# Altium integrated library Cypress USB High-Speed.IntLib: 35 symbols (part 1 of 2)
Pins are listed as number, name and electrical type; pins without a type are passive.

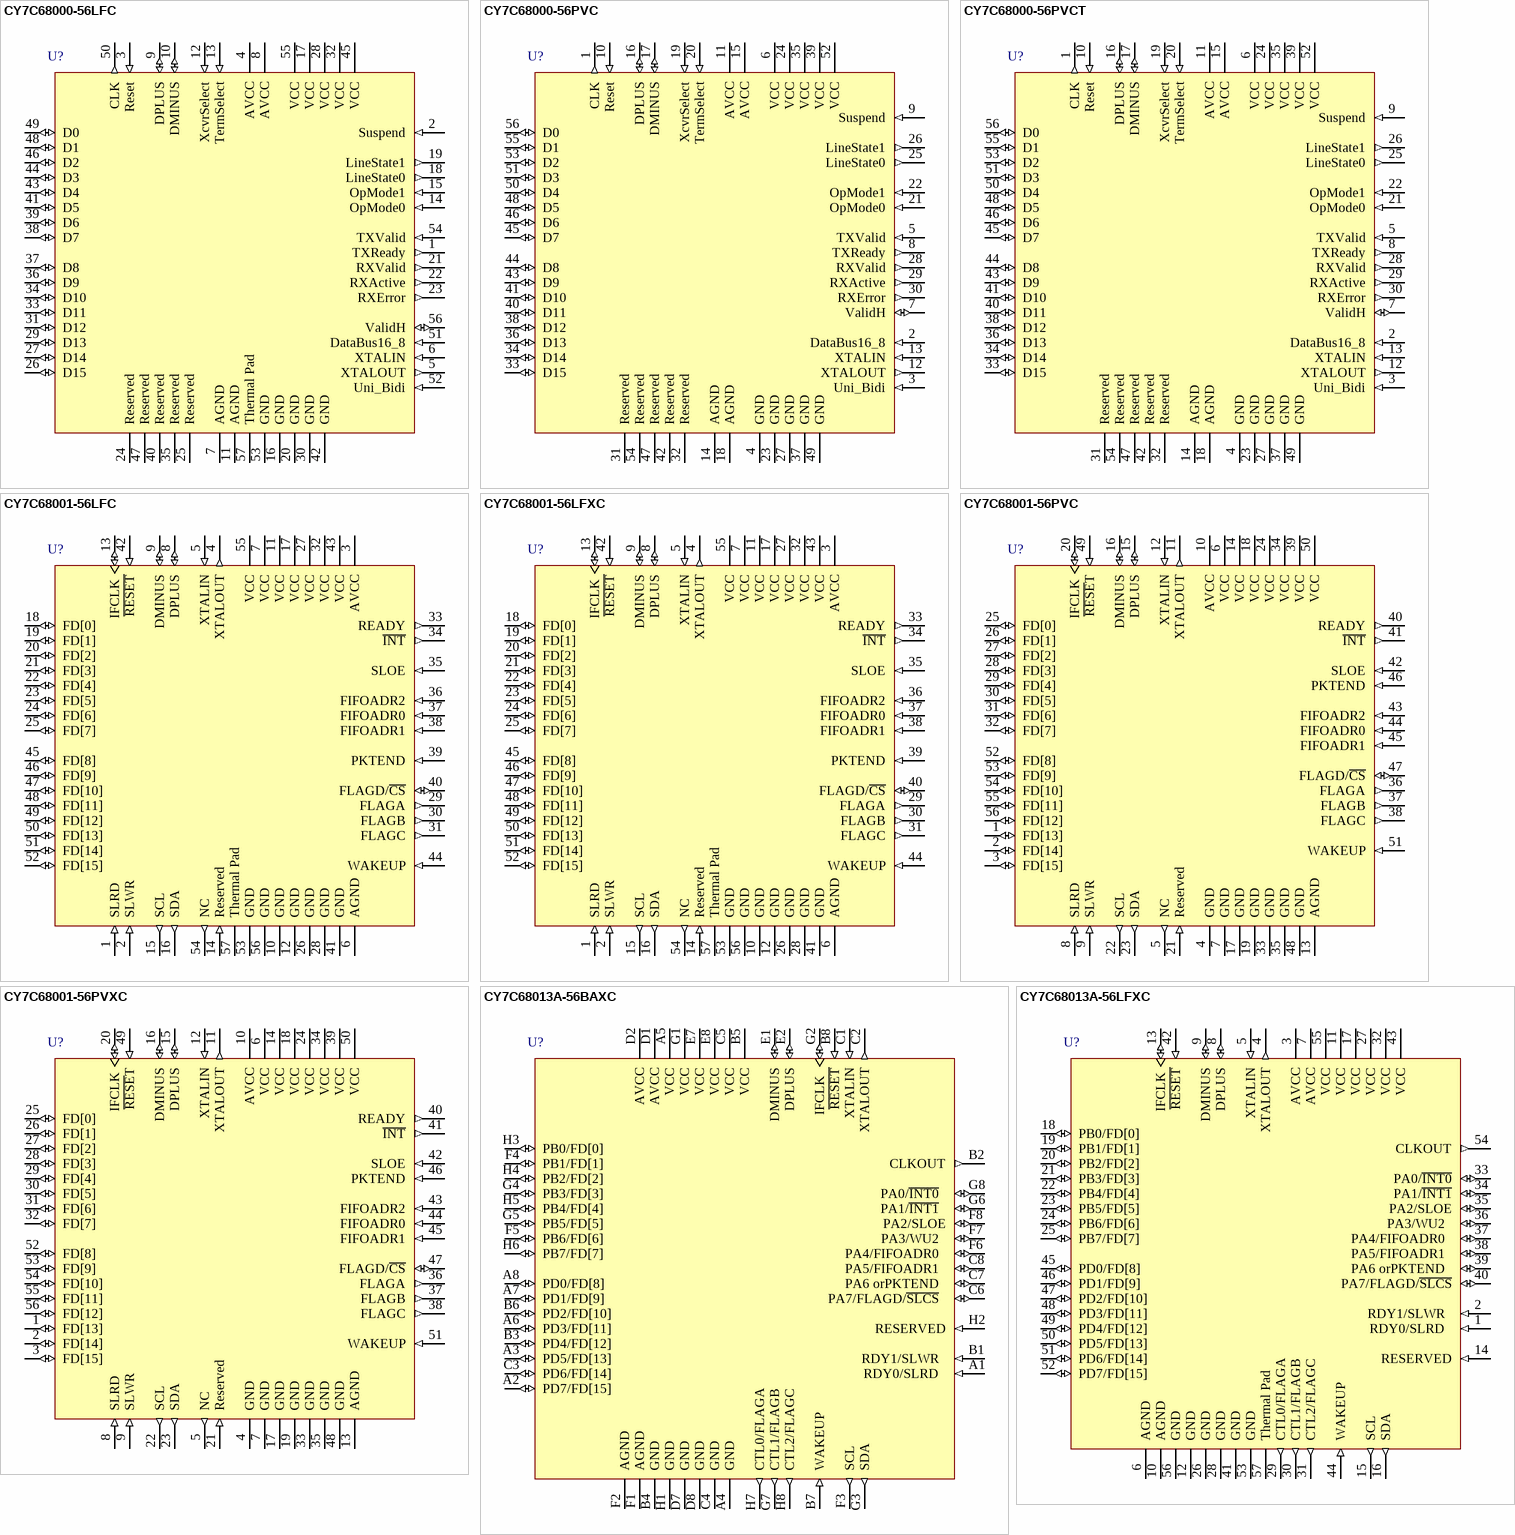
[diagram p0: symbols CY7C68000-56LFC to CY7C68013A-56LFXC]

## CY7C68000-56LFC
designator U?
TX2 USB2.0 Compliant with Transceiver Macrocell Interface Specification, 56-Pin QFN
footprint LS56B_N (QFN, 56-Leads, Body 8x8mm, Pitch 0.5mm, IPC Medium Density)
footprint LS56B_L (QFN, 56-Leads, Body 8x8mm, Pitch 0.5mm, IPC High Density)
footprint LS56B_M (QFN, 56-Leads, Body 8x8mm, Pitch 0.5mm, IPC Low Density)
pins: 1 TXReady (out), 2 Suspend (in), 3 Reset (in), 4 AVCC (power), 5 XTALOUT (out), 6 XTALIN (in), 7 AGND (power), 8 AVCC (power), 9 DPLUS (io), 10 DMINUS (io), 11 AGND (power), 12 XcvrSelect (in), 13 TermSelect (in), 14 OpMode0 (in), 15 OpMode1 (in), 16 GND (power), 17 VCC (power), 18 LineState0 (out), 19 LineState1 (out), 20 GND (power), 21 RXValid (out), 22 RXActive (out), 23 RXError (out), 24 Reserved, 25 Reserved, 26 D15 (io), 27 D14 (io), 28 VCC (power), 29 D13 (io), 30 GND (power), 31 D12 (io), 32 VCC (power), 33 D11 (io), 34 D10 (io), 35 Reserved, 36 D9 (io), 37 D8 (io), 38 D7 (io), 39 D6 (io), 40 Reserved, 41 D5 (io), 42 GND (power), 43 D4 (io), 44 D3 (io), 45 VCC (power), 46 D2 (io), 47 Reserved, 48 D1 (io), 49 D0 (io), 50 CLK (out), 51 DataBus16_8 (in), 52 Uni_Bidi (in), 53 GND (power), 54 TXValid (in), 55 VCC (power), 56 ValidH (io), 57 Thermal Pad (power)

## CY7C68000-56PVC
designator U?
TX2 USB2.0 Compliant with Transceiver Macrocell Interface Specification, 56-Pin SSOP
footprint O56 (SSOP; 56 Leads; Body Width 7.5 mm; Pitch 0.635 mm)
pins: 1 CLK (out), 2 DataBus16_8 (in), 3 Uni_Bidi (in), 4 GND (power), 5 TXValid (in), 6 VCC (power), 7 ValidH (io), 8 TXReady (out), 9 Suspend (in), 10 Reset (in), 11 AVCC (power), 12 XTALOUT (out), 13 XTALIN (in), 14 AGND (power), 15 AVCC (power), 16 DPLUS (io), 17 DMINUS (io), 18 AGND (power), 19 XcvrSelect (in), 20 TermSelect (in), 21 OpMode0 (in), 22 OpMode1 (in), 23 GND (power), 24 VCC (power), 25 LineState0 (out), 26 LineState1 (out), 27 GND (power), 28 RXValid (out), 29 RXActive (out), 30 RXError (out), 31 Reserved, 32 Reserved, 33 D15 (io), 34 D14 (io), 35 VCC (power), 36 D13 (io), 37 GND (power), 38 D12 (io), 39 VCC (power), 40 D11 (io), 41 D10 (io), 42 Reserved, 43 D9 (io), 44 D8 (io), 45 D7 (io), 46 D6 (io), 47 Reserved, 48 D5 (io), 49 GND (power), 50 D4 (io), 51 D3 (io), 52 VCC (power), 53 D2 (io), 54 Reserved, 55 D1 (io), 56 D0 (io)

## CY7C68000-56PVCT
designator U?
TX2 USB2.0 Compliant with Transceiver Macrocell Interface Specification, 56-Pin SSOP
footprint O56 (SSOP; 56 Leads; Body Width 7.5 mm; Pitch 0.635 mm)
pins: 1 CLK (out), 2 DataBus16_8 (in), 3 Uni_Bidi (in), 4 GND (power), 5 TXValid (in), 6 VCC (power), 7 ValidH (io), 8 TXReady (out), 9 Suspend (in), 10 Reset (in), 11 AVCC (power), 12 XTALOUT (out), 13 XTALIN (in), 14 AGND (power), 15 AVCC (power), 16 DPLUS (io), 17 DMINUS (io), 18 AGND (power), 19 XcvrSelect (in), 20 TermSelect (in), 21 OpMode0 (in), 22 OpMode1 (in), 23 GND (power), 24 VCC (power), 25 LineState0 (out), 26 LineState1 (out), 27 GND (power), 28 RXValid (out), 29 RXActive (out), 30 RXError (out), 31 Reserved, 32 Reserved, 33 D15 (io), 34 D14 (io), 35 VCC (power), 36 D13 (io), 37 GND (power), 38 D12 (io), 39 VCC (power), 40 D11 (io), 41 D10 (io), 42 Reserved, 43 D9 (io), 44 D8 (io), 45 D7 (io), 46 D6 (io), 47 Reserved, 48 D5 (io), 49 GND (power), 50 D4 (io), 51 D3 (io), 52 VCC (power), 53 D2 (io), 54 Reserved, 55 D1 (io), 56 D0 (io)

## CY7C68001-56LFC
designator U?
EZ-USB SX2 High-Speed USB Interface Device, 56-Pin QFN
footprint LF56A_N (QFN, 56-Leads, Body 8x8mm, Pitch 0.5mm, IPC Medium Density)
footprint LF56A_L (QFN, 56-Leads, Body 8x8mm, Pitch 0.5mm, IPC High Density)
footprint LF56A_M (QFN, 56-Leads, Body 8x8mm, Pitch 0.5mm, IPC Low Density)
pins: 1 SLRD (in), 2 SLWR (in), 3 AVCC (power), 4 XTALOUT (out), 5 XTALIN (in), 6 AGND (power), 7 VCC (power), 8 DPLUS (io), 9 DMINUS (io), 10 GND (power), 11 VCC (power), 12 GND (power), 13 IFCLK (io), 14 Reserved (in), 15 SCL (out), 16 SDA (out), 17 VCC (power), 18 FD[0] (io), 19 FD[1] (io), 20 FD[2] (io), 21 FD[3] (io), 22 FD[4] (io), 23 FD[5] (io), 24 FD[6] (io), 25 FD[7] (io), 26 GND (power), 27 VCC (power), 28 GND (power), 29 FLAGA (out), 30 FLAGB (out), 31 FLAGC (out), 32 VCC (power), 33 READY (out), 34 ~{INT} (out), 35 SLOE (in), 36 FIFOADR2 (in), 37 FIFOADR0 (in), 38 FIFOADR1 (in), 39 PKTEND (in), 40 FLAGD/~{CS} (io), 41 GND (power), 42 ~{RESET} (in), 43 VCC (power), 44 WAKEUP (in), 45 FD[8] (io), 46 FD[9] (io), 47 FD[10] (io), 48 FD[11] (io), 49 FD[12] (io), 50 FD[13] (io), 51 FD[14] (io), 52 FD[15] (io), 53 GND (power), 54 NC (out), 55 VCC (power), 56 GND (power), 57 Thermal Pad (power)

## CY7C68001-56LFXC
designator U?
EZ-USB SX2 High-Speed USB Interface Device, 56-Pin QFN, Pb-Free
footprint LF56A_N (QFN, 56-Leads, Body 8x8mm, Pitch 0.5mm, IPC Medium Density)
footprint LF56A_L (QFN, 56-Leads, Body 8x8mm, Pitch 0.5mm, IPC High Density)
footprint LF56A_M (QFN, 56-Leads, Body 8x8mm, Pitch 0.5mm, IPC Low Density)
pins: 1 SLRD (in), 2 SLWR (in), 3 AVCC (power), 4 XTALOUT (out), 5 XTALIN (in), 6 AGND (power), 7 VCC (power), 8 DPLUS (io), 9 DMINUS (io), 10 GND (power), 11 VCC (power), 12 GND (power), 13 IFCLK (io), 14 Reserved (in), 15 SCL (out), 16 SDA (out), 17 VCC (power), 18 FD[0] (io), 19 FD[1] (io), 20 FD[2] (io), 21 FD[3] (io), 22 FD[4] (io), 23 FD[5] (io), 24 FD[6] (io), 25 FD[7] (io), 26 GND (power), 27 VCC (power), 28 GND (power), 29 FLAGA (out), 30 FLAGB (out), 31 FLAGC (out), 32 VCC (power), 33 READY (out), 34 ~{INT} (out), 35 SLOE (in), 36 FIFOADR2 (in), 37 FIFOADR0 (in), 38 FIFOADR1 (in), 39 PKTEND (in), 40 FLAGD/~{CS} (io), 41 GND (power), 42 ~{RESET} (in), 43 VCC (power), 44 WAKEUP (in), 45 FD[8] (io), 46 FD[9] (io), 47 FD[10] (io), 48 FD[11] (io), 49 FD[12] (io), 50 FD[13] (io), 51 FD[14] (io), 52 FD[15] (io), 53 GND (power), 54 NC (out), 55 VCC (power), 56 GND (power), 57 Thermal Pad (power)

## CY7C68001-56PVC
designator U?
EZ-USB SX2 High-Speed USB Interface Device, 56-Pin SSOP
footprint O56 (SSOP; 56 Leads; Body Width 7.5 mm; Pitch 0.635 mm)
pins: 1 FD[13] (io), 2 FD[14] (io), 3 FD[15] (io), 4 GND (power), 5 NC (out), 6 VCC (power), 7 GND (power), 8 SLRD (in), 9 SLWR (in), 10 AVCC (power), 11 XTALOUT (out), 12 XTALIN (in), 13 AGND (power), 14 VCC (power), 15 DPLUS (io), 16 DMINUS (io), 17 GND (power), 18 VCC (power), 19 GND (power), 20 IFCLK (io), 21 Reserved (in), 22 SCL (out), 23 SDA (out), 24 VCC (power), 25 FD[0] (io), 26 FD[1] (io), 27 FD[2] (io), 28 FD[3] (io), 29 FD[4] (io), 30 FD[5] (io), 31 FD[6] (io), 32 FD[7] (io), 33 GND (power), 34 VCC (power), 35 GND (power), 36 FLAGA (out), 37 FLAGB (out), 38 FLAGC (out), 39 VCC (power), 40 READY (out), 41 ~{INT} (out), 42 SLOE (in), 43 FIFOADR2 (in), 44 FIFOADR0 (in), 45 FIFOADR1 (in), 46 PKTEND (in), 47 FLAGD/~{CS} (io), 48 GND (power), 49 ~{RESE}T (in), 50 VCC (power), 51 WAKEUP (in), 52 FD[8] (io), 53 FD[9] (io), 54 FD[10] (io), 55 FD[11] (io), 56 FD[12] (io)

## CY7C68001-56PVXC
designator U?
EZ-USB SX2 High-Speed USB Interface Device, 56-Pin SSOP, Pb-Free
footprint O56 (SSOP; 56 Leads; Body Width 7.5 mm; Pitch 0.635 mm)
pins: 1 FD[13] (io), 2 FD[14] (io), 3 FD[15] (io), 4 GND (power), 5 NC (out), 6 VCC (power), 7 GND (power), 8 SLRD (in), 9 SLWR (in), 10 AVCC (power), 11 XTALOUT (out), 12 XTALIN (in), 13 AGND (power), 14 VCC (power), 15 DPLUS (io), 16 DMINUS (io), 17 GND (power), 18 VCC (power), 19 GND (power), 20 IFCLK (io), 21 Reserved (in), 22 SCL (out), 23 SDA (out), 24 VCC (power), 25 FD[0] (io), 26 FD[1] (io), 27 FD[2] (io), 28 FD[3] (io), 29 FD[4] (io), 30 FD[5] (io), 31 FD[6] (io), 32 FD[7] (io), 33 GND (power), 34 VCC (power), 35 GND (power), 36 FLAGA (out), 37 FLAGB (out), 38 FLAGC (out), 39 VCC (power), 40 READY (out), 41 ~{INT} (out), 42 SLOE (in), 43 FIFOADR2 (in), 44 FIFOADR0 (in), 45 FIFOADR1 (in), 46 PKTEND (in), 47 FLAGD/~{CS} (io), 48 GND (power), 49 ~{RESE}T (in), 50 VCC (power), 51 WAKEUP (in), 52 FD[8] (io), 53 FD[9] (io), 54 FD[10] (io), 55 FD[11] (io), 56 FD[12] (io)

## CY7C68013A-56BAXC
designator U?
EZ-USB FX2LP USB Microcontroller Ideal for Non-Battery Powered Applications,16K RAM, 24 I/Os, 56-Pin VFBGA, Pb-Free, Commercial Grade
footprint BZ56 (BGA, 56-Leads, Body 5x5mm, Pitch 0.5mm)
pins: A1  RDY0/SLRD   (in), A2 PD7/FD[15]   (io) "Port D", A3 PD5/FD[13]   (io) "Port D", A4 GND (power), A5 VCC (power), A6 PD3/FD[11]   (io) "Port D", A7 PD1/FD[9]   (io) "Port D", A8 PD0/FD[8]   (io) "Port D", B1  RDY1/SLWR   (in), B2 CLKOUT (out), B3 PD4/FD[12]   (io) "Port D", B4 GND (power), B5 VCC (power), B6 PD2/FD[10]   (io) "Port D", B7 WAKEUP (in), B8 ~{RESET} (in), C1 XTALIN (in), C2 XTALOUT (out), C3 PD6/FD[14]   (io) "Port D", C4 GND (power), C5 VCC (power), C6 PA7/FLAGD/~{SLCS}   (io) "Port A", C7 PA6 orPKTEND   (io) "Port A", C8 PA5/FIFOADR1   (io) "Port A", D1 AVCC (power), D2 AVCC (power), D7 GND (power), D8 GND (power), E1 DMINUS (io), E2 DPLUS (io), E7 VCC (power), E8 VCC (power), F1 AGND (power), F2 AGND (power), F3 SCL (out), F4 PB1/FD[1]   (io) "Port B", F5 PB6/FD[6]   (io) "Port B", F6 PA4/FIFOADR0   (io) "Port A", F7 PA3/WU2   (io) "Port A", F8 PA2/SLOE (io) "Port A", G1 VCC (power), G2  IFCLK  (io), G3 SDA (out), G4 PB3/FD[3]   (io) "Port B", G5 PB5/FD[5]   (io) "Port B", G6 PA1/~{INT1}   (io) "Port A", G7 CTL1/FLAGB   (out), G8 PA0/~{INT0}   (io) "Port A", H1 GND (power), H2 RESERVED (in), H3 PB0/FD[0]   (io) "Port B", H4 PB2/FD[2]   (io) "Port B", H5 PB4/FD[4]   (io) "Port B", H6 PB7/FD[7]   (io) "Port B", H7 CTL0/FLAGA   (out), H8 CTL2/FLAGC   (out)

## CY7C68013A-56LFXC
designator U?
EZ-USB FX2LP USB Microcontroller Ideal for Non-Battery Powered Applications,16K RAM, 24 I/Os, 56-Pin QFN, Pb-Free, Commercial Grade
footprint LF56A_N (QFN, 56-Leads, Body 8x8mm, Pitch 0.5mm, IPC Medium Density)
footprint LF56A_L (QFN, 56-Leads, Body 8x8mm, Pitch 0.5mm, IPC High Density)
footprint LF56A_M (QFN, 56-Leads, Body 8x8mm, Pitch 0.5mm, IPC Low Density)
pins: 1  RDY0/SLRD   (in), 2  RDY1/SLWR   (in), 3 AVCC (power), 4 XTALOUT (out), 5 XTALIN (in), 6 AGND (power), 7 AVCC (power), 8 DPLUS (io), 9 DMINUS (io), 10 AGND (power), 11 VCC (power), 12 GND (power), 13  IFCLK (io), 14 RESERVED (in), 15 SCL (out), 16 SDA (out), 17 VCC (power), 18 PB0/FD[0]   (io) "Port B", 19 PB1/FD[1]   (io) "Port B", 20 PB2/FD[2]   (io) "Port B", 21 PB3/FD[3]   (io) "Port B", 22 PB4/FD[4]   (io) "Port B", 23 PB5/FD[5]   (io) "Port B", 24 PB6/FD[6]   (io) "Port B", 25 PB7/FD[7]   (io) "Port B", 26 GND (power), 27 VCC (power), 28 GND (power), 29 CTL0/FLAGA   (out), 30 CTL1/FLAGB   (out), 31 CTL2/FLAGC   (out), 32 VCC (power), 33 PA0/~{INT0} (io) "Port A", 34 PA1/~{INT1} (io) "Port A", 35 PA2/SLOE (io) "Port A", 36 PA3/WU2   (io) "Port A", 37 PA4/FIFOADR0   (io) "Port A", 38 PA5/FIFOADR1   (io) "Port A", 39 PA6 orPKTEND   (io) "Port A", 40 PA7/FLAGD/~{SLCS} (io) "Port A", 41 GND (power), 42 ~{RESET} (in), 43 VCC (power), 44 WAKEUP (in), 45 PD0/FD[8]   (io) "Port D", 46 PD1/FD[9]   (io) "Port D", 47 PD2/FD[10]   (io) "Port D", 48 PD3/FD[11]   (io) "Port D", 49 PD4/FD[12]   (io) "Port D", 50 PD5/FD[13]   (io) "Port D", 51 PD6/FD[14]   (io) "Port D", 52 PD7/FD[15]   (io) "Port D", 53 GND (power), 54 CLKOUT (out), 55 VCC (power), 56 GND (power), 57 Thermal Pad (power)

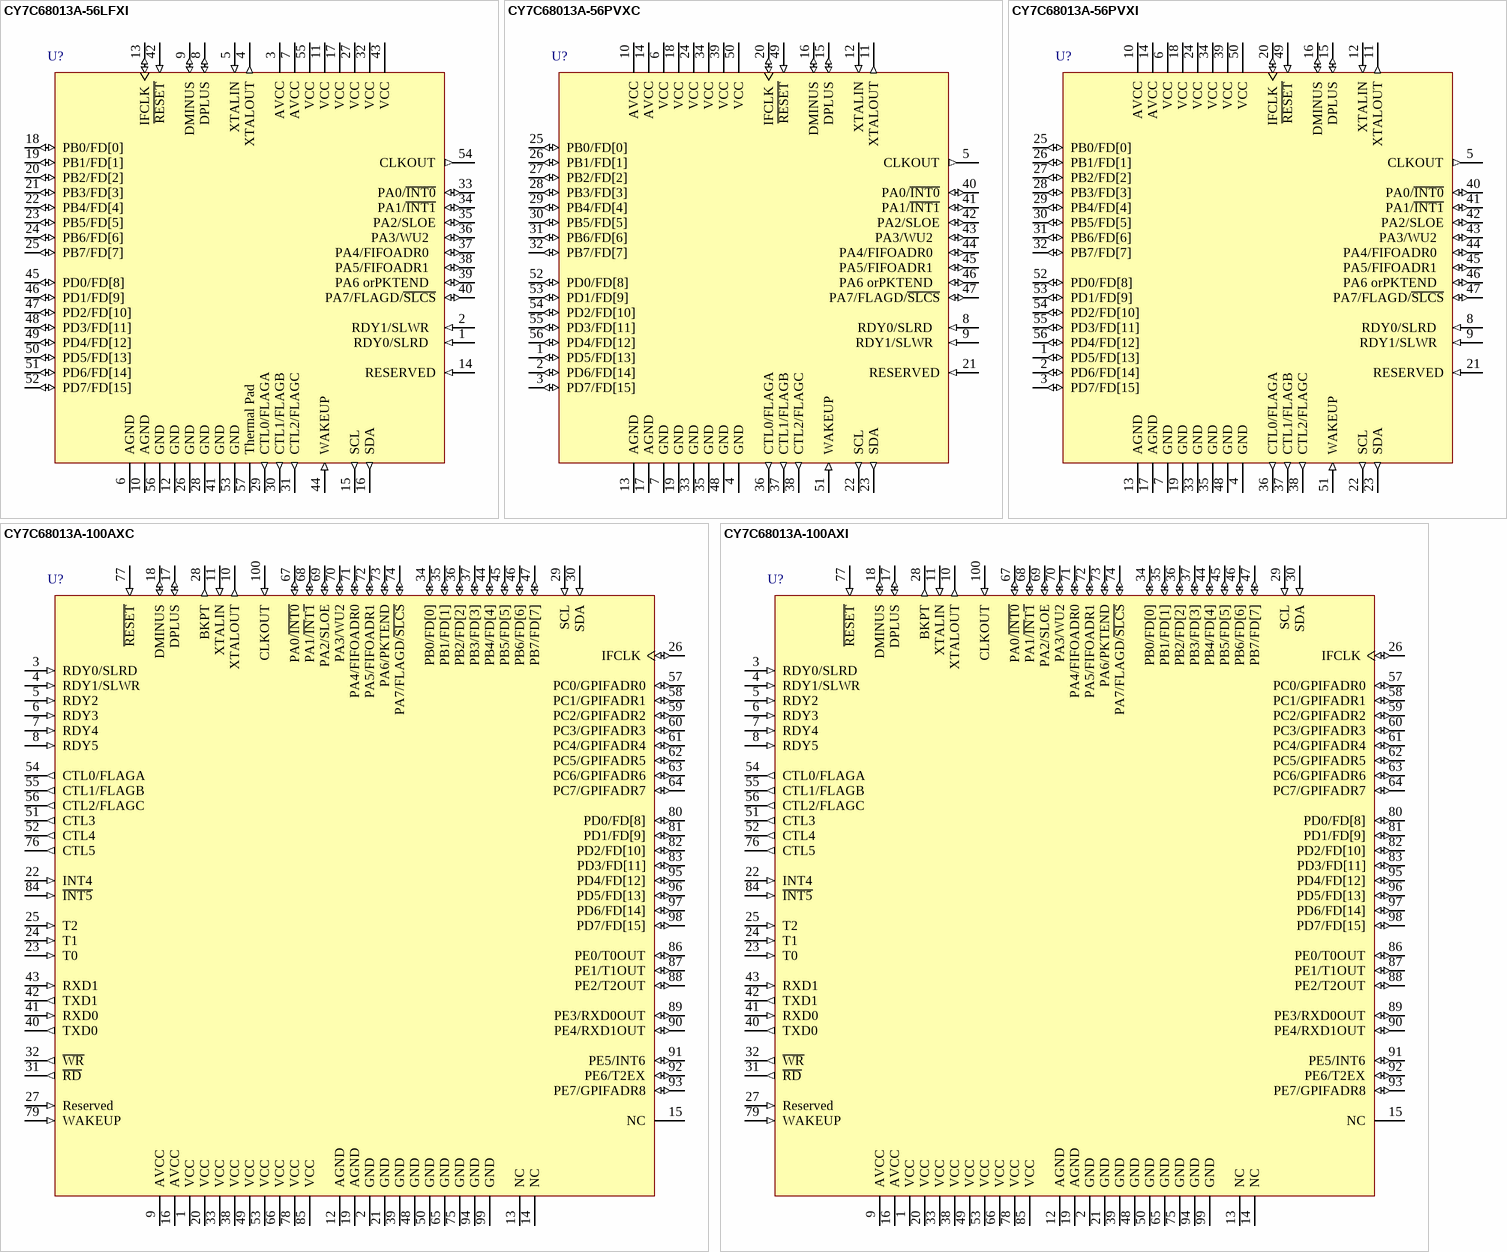
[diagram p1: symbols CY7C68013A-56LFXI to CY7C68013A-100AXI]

## CY7C68013A-56LFXI
designator U?
EZ-USB FX2LP USB Microcontroller Ideal for Non-Battery Powered Applications,16K RAM, 24 I/Os, 56-Pin QFN, Pb-Free, Industrial Grade
footprint LF56A_N (QFN, 56-Leads, Body 8x8mm, Pitch 0.5mm, IPC Medium Density)
footprint LF56A_L (QFN, 56-Leads, Body 8x8mm, Pitch 0.5mm, IPC High Density)
footprint LF56A_M (QFN, 56-Leads, Body 8x8mm, Pitch 0.5mm, IPC Low Density)
pins: 1  RDY0/SLRD   (in), 2  RDY1/SLWR   (in), 3 AVCC (power), 4 XTALOUT (out), 5 XTALIN (in), 6 AGND (power), 7 AVCC (power), 8 DPLUS (io), 9 DMINUS (io), 10 AGND (power), 11 VCC (power), 12 GND (power), 13  IFCLK (io), 14 RESERVED (in), 15 SCL (out), 16 SDA (out), 17 VCC (power), 18 PB0/FD[0]   (io) "Port B", 19 PB1/FD[1]   (io) "Port B", 20 PB2/FD[2]   (io) "Port B", 21 PB3/FD[3]   (io) "Port B", 22 PB4/FD[4]   (io) "Port B", 23 PB5/FD[5]   (io) "Port B", 24 PB6/FD[6]   (io) "Port B", 25 PB7/FD[7]   (io) "Port B", 26 GND (power), 27 VCC (power), 28 GND (power), 29 CTL0/FLAGA   (out), 30 CTL1/FLAGB   (out), 31 CTL2/FLAGC   (out), 32 VCC (power), 33 PA0/~{INT0} (io) "Port A", 34 PA1/~{INT1} (io) "Port A", 35 PA2/SLOE (io) "Port A", 36 PA3/WU2   (io) "Port A", 37 PA4/FIFOADR0   (io) "Port A", 38 PA5/FIFOADR1   (io) "Port A", 39 PA6 orPKTEND   (io) "Port A", 40 PA7/FLAGD/~{SLCS} (io) "Port A", 41 GND (power), 42 ~{RESET} (in), 43 VCC (power), 44 WAKEUP (in), 45 PD0/FD[8]   (io) "Port D", 46 PD1/FD[9]   (io) "Port D", 47 PD2/FD[10]   (io) "Port D", 48 PD3/FD[11]   (io) "Port D", 49 PD4/FD[12]   (io) "Port D", 50 PD5/FD[13]   (io) "Port D", 51 PD6/FD[14]   (io) "Port D", 52 PD7/FD[15]   (io) "Port D", 53 GND (power), 54 CLKOUT (out), 55 VCC (power), 56 GND (power), 57 Thermal Pad (power)

## CY7C68013A-56PVXC
designator U?
EZ-USB FX2LP USB Microcontroller Ideal for Non-Battery Powered Applications,16K RAM, 24 I/Os, 56-Pin SSOP, Pb-Free, Commercial Grade
footprint O56 (SSOP; 56 Leads; Body Width 7.5 mm; Pitch 0.635 mm)
pins: 1 PD5/FD[13]   (io) "Port D", 2 PD6/FD[14]   (io) "Port D", 3 PD7/FD[15]   (io) "Port D", 4 GND (power), 5 CLKOUT (out), 6 VCC (power), 7 GND (power), 8  RDY0/SLRD   (in), 9  RDY1/SLWR   (in), 10 AVCC (power), 11 XTALOUT (out), 12 XTALIN (in), 13 AGND (power), 14 AVCC (power), 15 DPLUS (io), 16 DMINUS (io), 17 AGND (power), 18 VCC (power), 19 GND (power), 20  IFCLK (io), 21 RESERVED (in), 22 SCL (out), 23 SDA (out), 24 VCC (power), 25 PB0/FD[0]   (io) "Port B", 26 PB1/FD[1]   (io) "Port B", 27 PB2/FD[2]   (io) "Port B", 28 PB3/FD[3]   (io) "Port B", 29 PB4/FD[4]   (io) "Port B", 30 PB5/FD[5]   (io) "Port B", 31 PB6/FD[6]   (io) "Port B", 32 PB7/FD[7]   (io) "Port B", 33 GND (power), 34 VCC (power), 35 GND (power), 36 CTL0/FLAGA   (out), 37 CTL1/FLAGB   (out), 38 CTL2/FLAGC   (out), 39 VCC (power), 40 PA0/~{INT0} (io) "Port A", 41 PA1/~{INT1} (io) "Port A", 42 PA2/SLOE (io) "Port A", 43 PA3/WU2   (io) "Port A", 44 PA4/FIFOADR0   (io) "Port A", 45 PA5/FIFOADR1   (io) "Port A", 46 PA6 orPKTEND   (io) "Port A", 47 PA7/FLAGD/~{SLCS} (io) "Port A", 48 GND (power), 49 ~{RESET} (in), 50 VCC (power), 51 WAKEUP (in), 52 PD0/FD[8]   (io) "Port D", 53 PD1/FD[9]   (io) "Port D", 54 PD2/FD[10]   (io) "Port D", 55 PD3/FD[11]   (io) "Port D", 56 PD4/FD[12]   (io) "Port D"

## CY7C68013A-56PVXI
designator U?
EZ-USB FX2LP USB Microcontroller Ideal for Non-Battery Powered Applications,16K RAM, 24 I/Os, 56-Pin SSOP, Pb-Free, Industrial Grade
footprint O56 (SSOP; 56 Leads; Body Width 7.5 mm; Pitch 0.635 mm)
pins: 1 PD5/FD[13]   (io) "Port D", 2 PD6/FD[14]   (io) "Port D", 3 PD7/FD[15]   (io) "Port D", 4 GND (power), 5 CLKOUT (out), 6 VCC (power), 7 GND (power), 8  RDY0/SLRD   (in), 9  RDY1/SLWR   (in), 10 AVCC (power), 11 XTALOUT (out), 12 XTALIN (in), 13 AGND (power), 14 AVCC (power), 15 DPLUS (io), 16 DMINUS (io), 17 AGND (power), 18 VCC (power), 19 GND (power), 20  IFCLK (io), 21 RESERVED (in), 22 SCL (out), 23 SDA (out), 24 VCC (power), 25 PB0/FD[0]   (io) "Port B", 26 PB1/FD[1]   (io) "Port B", 27 PB2/FD[2]   (io) "Port B", 28 PB3/FD[3]   (io) "Port B", 29 PB4/FD[4]   (io) "Port B", 30 PB5/FD[5]   (io) "Port B", 31 PB6/FD[6]   (io) "Port B", 32 PB7/FD[7]   (io) "Port B", 33 GND (power), 34 VCC (power), 35 GND (power), 36 CTL0/FLAGA   (out), 37 CTL1/FLAGB   (out), 38 CTL2/FLAGC   (out), 39 VCC (power), 40 PA0/~{INT0} (io) "Port A", 41 PA1/~{INT1} (io) "Port A", 42 PA2/SLOE (io) "Port A", 43 PA3/WU2   (io) "Port A", 44 PA4/FIFOADR0   (io) "Port A", 45 PA5/FIFOADR1   (io) "Port A", 46 PA6 orPKTEND   (io) "Port A", 47 PA7/FLAGD/~{SLCS} (io) "Port A", 48 GND (power), 49 ~{RESET} (in), 50 VCC (power), 51 WAKEUP (in), 52 PD0/FD[8]   (io) "Port D", 53 PD1/FD[9]   (io) "Port D", 54 PD2/FD[10]   (io) "Port D", 55 PD3/FD[11]   (io) "Port D", 56 PD4/FD[12]   (io) "Port D"

## CY7C68013A-100AXC
designator U?
EZ-USB FX2LP USB Microcontroller Ideal for Non-Battery Powered Applications,16K RAM, 40 I/Os, 100-Pin TQFP, Pb-Free, Commercial Grade
footprint A101_N (Thin QFP, 100-Leads, Body 20x14mm, Pitch 0.65mm, IPC Medium Density)
footprint A101_L (Thin QFP, 100-Leads, Body 20x14mm, Pitch 0.65mm, IPC High Density)
footprint A101_M (Thin QFP, 100-Leads, Body 20x14mm, Pitch 0.65mm, IPC Low Density)
pins: 1 VCC (power), 2 GND (power), 3 RDY0/SLRD (in), 4 RDY1/SLWR (in), 5 RDY2 (in), 6 RDY3 (in), 7 RDY4 (in), 8 RDY5 (in), 9 AVCC (power), 10 XTALOUT (out), 11 XTALIN (in), 12 AGND (power), 13 NC, 14 NC, 15 NC, 16 AVCC (power), 17 DPLUS (io), 18 DMINUS (io), 19 AGND (power), 20 VCC (power), 21 GND (power), 22 INT4 (in), 23 T0 (in), 24 T1 (in), 25 T2 (in), 26 IFCLK (io), 27 Reserved (in), 28 BKPT (out), 29 SCL (in), 30 SDA (in), 31 ~{RD} (out), 32 ~{WR} (out), 33 VCC (power), 34 PB0/FD[0] (io) "Port B", 35 PB1/FD[1] (io) "Port B", 36 PB2/FD[2] (io) "Port B", 37 PB3/FD[3] (io) "Port B", 38 VCC (power), 39 GND (power), 40 TXD0 (out), 41 RXD0 (in), 42 TXD1 (out), 43 RXD1 (in), 44 PB4/FD[4] (io) "Port B", 45 PB5/FD[5] (io) "Port B", 46 PB6/FD[6] (io) "Port B", 47 PB7/FD[7] (io) "Port B", 48 GND (power), 49 VCC (power), 50 GND (power), 51 CTL3 (out), 52 CTL4 (out), 53 VCC (power), 54 CTL0/FLAGA (out), 55 CTL1/FLAGB (out), 56 CTL2/FLAGC (out), 57 PC0/GPIFADR0 (io) "Port C", 58 PC1/GPIFADR1 (io) "Port C", 59 PC2/GPIFADR2 (io) "Port C", 60 PC3/GPIFADR3 (io) "Port C", 61 PC4/GPIFADR4 (io) "Port C", 62 PC5/GPIFADR5 (io) "Port C", 63 PC6/GPIFADR6 (io) "Port C", 64 PC7/GPIFADR7 (io) "Port C", 65 GND (power), 66 VCC (power), 67 PA0/~{INT0} (io) "Port A", 68 PA1/~{IN}T~{1} (io) "Port A", 69 PA2/SLOE (io) "Port A", 70 PA3/WU2 (io) "Port A", 71 PA4/FIFOADR0 (io) "Port A", 72 PA5/FIFOADR1 (io) "Port A", 73 PA6/PKTEND (io) "Port A", 74 PA7/FLAGD/~{SLCS} (io) "Port A", 75 GND (power), 76 CTL5 (out), 77 ~{RESET} (in), 78 VCC (power), 79 WAKEUP (in), 80 PD0/FD[8] (io) "Port D", 81 PD1/FD[9] (io) "Port D", 82 PD2/FD[10] (io) "Port D", 83 PD3/FD[11] (io) "Port D", 84 ~{INT5} (in), 85 VCC (power), 86 PE0/T0OUT (io) "Port E", 87 PE1/T1OUT (io) "Port E", 88 PE2/T2OUT (io) "Port E", 89 PE3/RXD0OUT (io) "Port E", 90 PE4/RXD1OUT (io) "Port E", 91 PE5/INT6 (io) "Port E", 92 PE6/T2EX (io) "Port E", 93 PE7/GPIFADR8 (io) "Port E", 94 GND (power), 95 PD4/FD[12] (io) "Port D", 96 PD5/FD[13] (io) "Port D", 97 PD6/FD[14] (io) "Port D", 98 PD7/FD[15] (io) "Port D", 99 GND (power), 100 CLKOUT (in)

## CY7C68013A-100AXI
designator U?
EZ-USB FX2LP USB Microcontroller Ideal for Non-Battery Powered Applications,16K RAM, 40 I/Os, 100-Pin TQFP, Pb-Free, Commercial Grade
footprint A101_N (Thin QFP, 100-Leads, Body 20x14mm, Pitch 0.65mm, IPC Medium Density)
footprint A101_L (Thin QFP, 100-Leads, Body 20x14mm, Pitch 0.65mm, IPC High Density)
footprint A101_M (Thin QFP, 100-Leads, Body 20x14mm, Pitch 0.65mm, IPC Low Density)
pins: 1 VCC (power), 2 GND (power), 3 RDY0/SLRD (in), 4 RDY1/SLWR (in), 5 RDY2 (in), 6 RDY3 (in), 7 RDY4 (in), 8 RDY5 (in), 9 AVCC (power), 10 XTALOUT (out), 11 XTALIN (in), 12 AGND (power), 13 NC, 14 NC, 15 NC, 16 AVCC (power), 17 DPLUS (io), 18 DMINUS (io), 19 AGND (power), 20 VCC (power), 21 GND (power), 22 INT4 (in), 23 T0 (in), 24 T1 (in), 25 T2 (in), 26 IFCLK (io), 27 Reserved (in), 28 BKPT (out), 29 SCL (in), 30 SDA (in), 31 ~{RD} (out), 32 ~{WR} (out), 33 VCC (power), 34 PB0/FD[0] (io) "Port B", 35 PB1/FD[1] (io) "Port B", 36 PB2/FD[2] (io) "Port B", 37 PB3/FD[3] (io) "Port B", 38 VCC (power), 39 GND (power), 40 TXD0 (out), 41 RXD0 (in), 42 TXD1 (out), 43 RXD1 (in), 44 PB4/FD[4] (io) "Port B", 45 PB5/FD[5] (io) "Port B", 46 PB6/FD[6] (io) "Port B", 47 PB7/FD[7] (io) "Port B", 48 GND (power), 49 VCC (power), 50 GND (power), 51 CTL3 (out), 52 CTL4 (out), 53 VCC (power), 54 CTL0/FLAGA (out), 55 CTL1/FLAGB (out), 56 CTL2/FLAGC (out), 57 PC0/GPIFADR0 (io) "Port C", 58 PC1/GPIFADR1 (io) "Port C", 59 PC2/GPIFADR2 (io) "Port C", 60 PC3/GPIFADR3 (io) "Port C", 61 PC4/GPIFADR4 (io) "Port C", 62 PC5/GPIFADR5 (io) "Port C", 63 PC6/GPIFADR6 (io) "Port C", 64 PC7/GPIFADR7 (io) "Port C", 65 GND (power), 66 VCC (power), 67 PA0/~{INT0} (io) "Port A", 68 PA1/~{IN}T~{1} (io) "Port A", 69 PA2/SLOE (io) "Port A", 70 PA3/WU2 (io) "Port A", 71 PA4/FIFOADR0 (io) "Port A", 72 PA5/FIFOADR1 (io) "Port A", 73 PA6/PKTEND (io) "Port A", 74 PA7/FLAGD/~{SLCS} (io) "Port A", 75 GND (power), 76 CTL5 (out), 77 ~{RESET} (in), 78 VCC (power), 79 WAKEUP (in), 80 PD0/FD[8] (io) "Port D", 81 PD1/FD[9] (io) "Port D", 82 PD2/FD[10] (io) "Port D", 83 PD3/FD[11] (io) "Port D", 84 ~{INT5} (in), 85 VCC (power), 86 PE0/T0OUT (io) "Port E", 87 PE1/T1OUT (io) "Port E", 88 PE2/T2OUT (io) "Port E", 89 PE3/RXD0OUT (io) "Port E", 90 PE4/RXD1OUT (io) "Port E", 91 PE5/INT6 (io) "Port E", 92 PE6/T2EX (io) "Port E", 93 PE7/GPIFADR8 (io) "Port E", 94 GND (power), 95 PD4/FD[12] (io) "Port D", 96 PD5/FD[13] (io) "Port D", 97 PD6/FD[14] (io) "Port D", 98 PD7/FD[15] (io) "Port D", 99 GND (power), 100 CLKOUT (in)

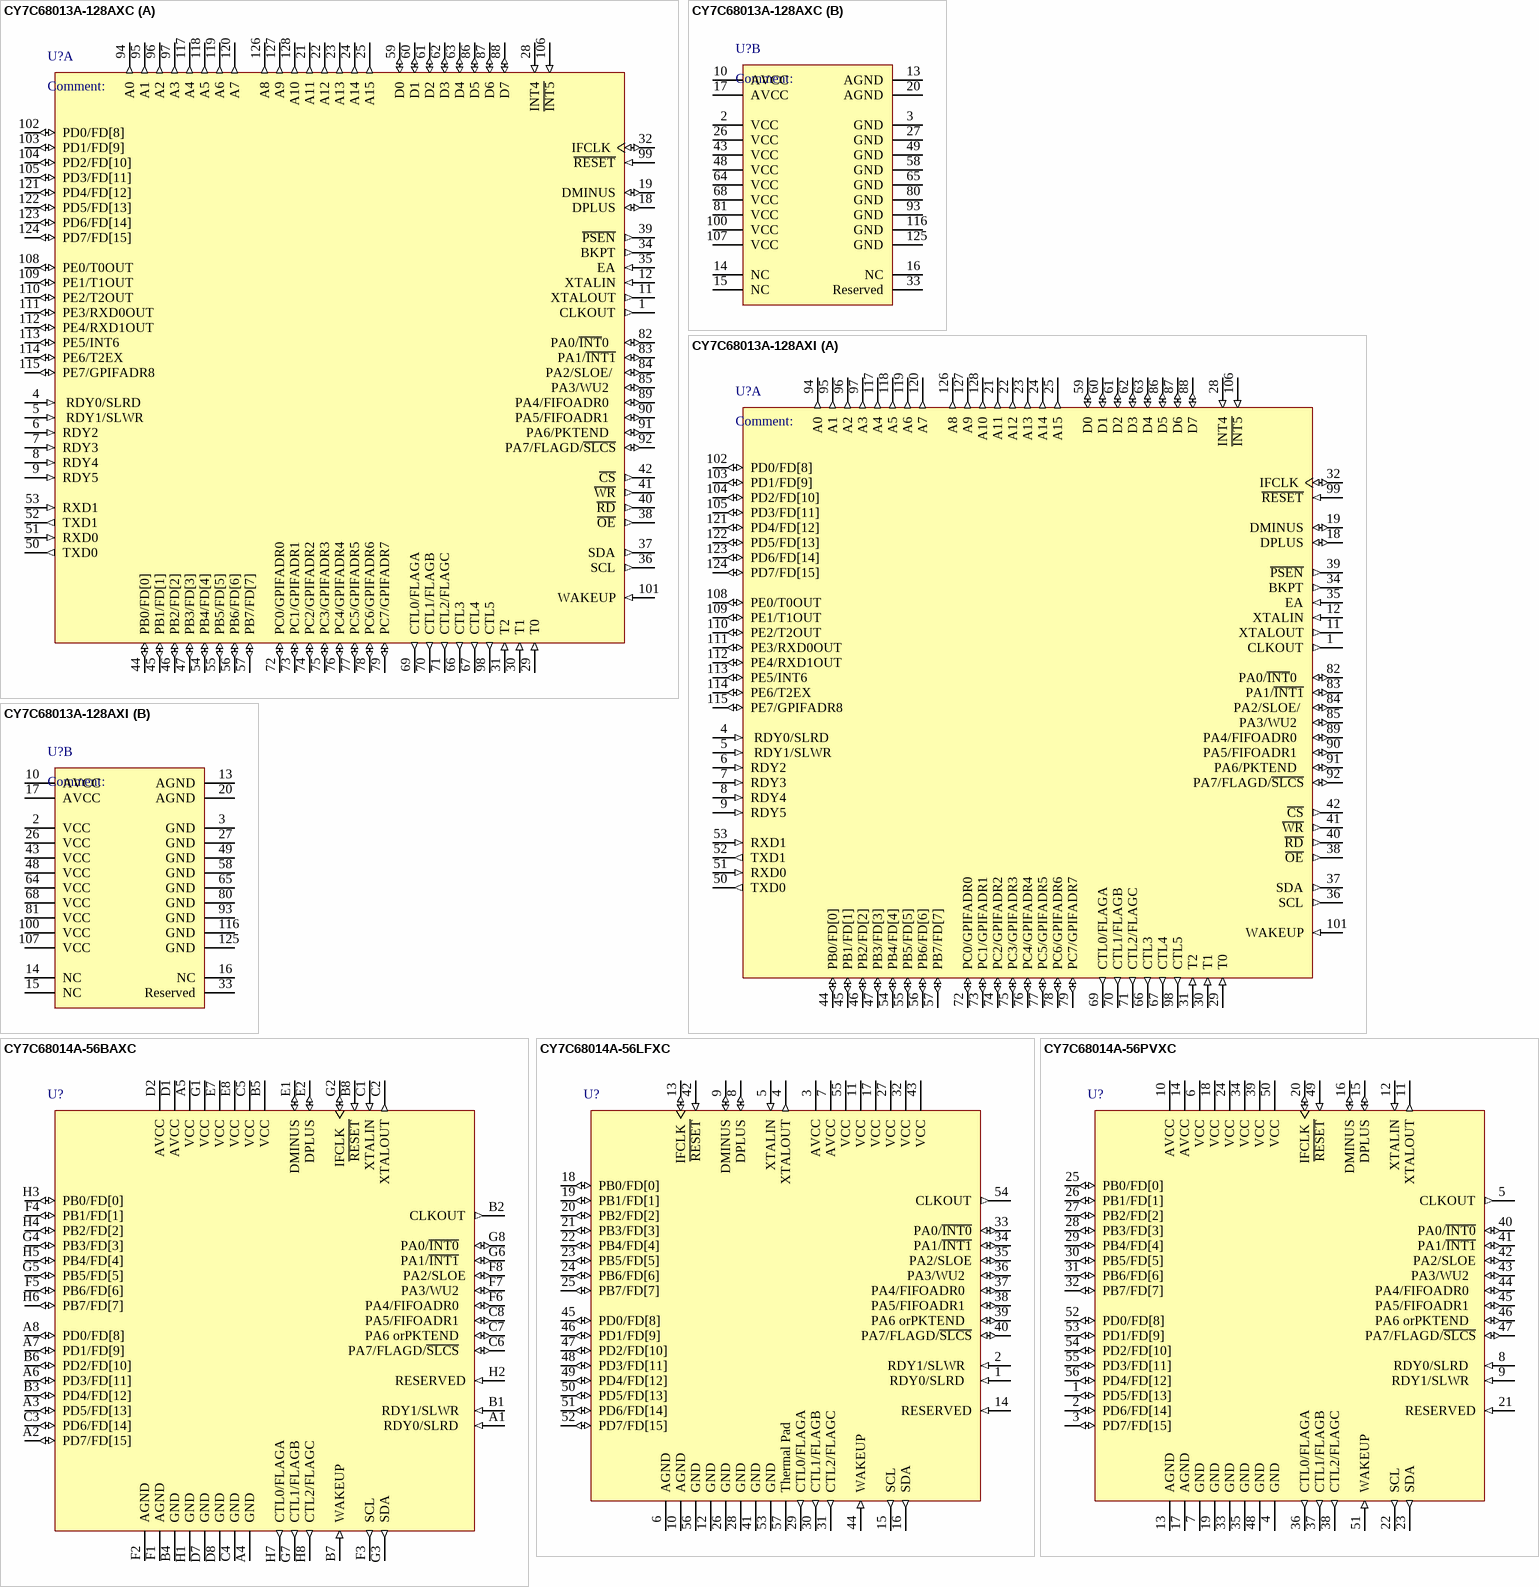
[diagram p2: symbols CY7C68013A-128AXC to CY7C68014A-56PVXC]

## CY7C68013A-128AXC
designator U?
EZ-USB FX2LP USB Microcontroller Ideal for Non-Battery Powered Applications,16K RAM, 40 I/Os, 128-Pin TQFP, Pb-Free, Commercial Grade
footprint A128_N (Thin QFP, 128-Leads, Body 20x14 mm, Pitch 0.5mm, IPC Medium Density)
footprint A128_L (Thin QFP, 128-Leads, Body 20x14 mm, Pitch 0.5mm, IPC High Density)
footprint A128_M (Thin QFP, 128-Leads, Body 20x14 mm, Pitch 0.5mm, IPC Low Density)
part A pins: 1 CLKOUT (out), 4  RDY0/SLRD   (in), 5  RDY1/SLWR   (in), 6 RDY2 (in), 7 RDY3 (in), 8 RDY4 (in), 9 RDY5 (in), 11 XTALOUT (out), 12 XTALIN (in), 18 DPLUS (io), 19 DMINUS (io), 21 A11 (out), 22 A12 (out), 23 A13 (out), 24 A14 (out), 25 A15 (out), 28 INT4 (in), 29 T0 (in), 30 T1 (in), 31 T2 (in), 32  IFCLK (io), 34 BKPT (out), 35 EA (in), 36 SCL (out), 37 SDA (out), 38 ~{OE} (out), 39 ~{PSEN} (out), 40 ~{RD} (out), 41 ~{WR} (out), 42 ~{CS} (out), 44 PB0/FD[0]   (io), 45 PB1/FD[1]   (io), 46 PB2/FD[2]   (io), 47 PB3/FD[3]   (io), 50 TXD0 (out), 51 RXD0 (in), 52 TXD1 (out), 53 RXD1 (in), 54 PB4/FD[4]   (io), 55 PB5/FD[5]   (io), 56 PB6/FD[6]   (io), 57 PB7/FD[7]   (io), 59 D0 (io), 60 D1 (io), 61 D2 (io), 62 D3 (io), 63 D4 (io), 66 CTL3 (out), 67 CTL4 (out), 69 CTL0/FLAGA   (out), 70 CTL1/FLAGB   (out), 71 CTL2/FLAGC   (out), 72 PC0/GPIFADR0   (io), 73 PC1/GPIFADR1   (io), 74 PC2/GPIFADR2   (io), 75 PC3/GPIFADR3   (io), 76 PC4/GPIFADR4   (io), 77 PC5/GPIFADR5   (io), 78 PC6/GPIFADR6   (io), 79 PC7/GPIFADR7   (io), 82 PA0/~{INT}0   (io), 83 PA1/~{INT1} (io), 84 PA2/SLOE/  (io), 85 PA3/WU2   (io), 86 D5 (io), 87 D6 (io), 88 D7 (io), 89 PA4/FIFOADR0   (io), 90 PA5/FIFOADR1   (io), 91 PA6/PKTEND   (io), 92 PA7/FLAGD/~{SLCS} (io), 94 A0 (out), 95 A1 (out), 96 A2 (out), 97 A3 (out), 98 CTL5 (out), 99 ~{RESET} (in), 101 WAKEUP (in), 102 PD0/FD[8]   (io), 103 PD1/FD[9]   (io), 104 PD2/FD[10]   (io), 105 PD3/FD[11]   (io), 106 ~{INT5} (in), 108 PE0/T0OUT   (io), 109 PE1/T1OUT   (io), 110 PE2/T2OUT   (io), 111 PE3/RXD0OUT   (io), 112 PE4/RXD1OUT   (io), 113 PE5/INT6   (io), 114 PE6/T2EX   (io), 115 PE7/GPIFADR8   (io), 117 A4 (out), 118 A5 (out), 119 A6 (out), 120 A7 (out), 121 PD4/FD[12]   (io), 122 PD5/FD[13]   (io), 123 PD6/FD[14]   (io), 124 PD7/FD[15]   (io), 126 A8 (out), 127 A9 (out), 128 A10 (out)
part B pins: 2 VCC (power), 3 GND (power), 10 AVCC (power), 13 AGND (power), 14 NC, 15 NC, 16 NC, 17 AVCC (power), 20 AGND (power), 26 VCC (power), 27 GND (power), 33 Reserved (power), 43 VCC (power), 48 VCC (power), 49 GND (power), 58 GND (power), 64 VCC (power), 65 GND (power), 68 VCC (power), 80 GND (power), 81 VCC (power), 93 GND (power), 100 VCC (power), 107 VCC (power), 116 GND (power), 125 GND (power)

## CY7C68013A-128AXI
designator U?
EZ-USB FX2LP USB Microcontroller Ideal for Non-Battery Powered Applications,16K RAM, 40 I/Os, 128-Pin TQFP, Pb-Free, Industrial Grade
footprint A128_N (Thin QFP, 128-Leads, Body 20x14 mm, Pitch 0.5mm, IPC Medium Density)
footprint A128_L (Thin QFP, 128-Leads, Body 20x14 mm, Pitch 0.5mm, IPC High Density)
footprint A128_M (Thin QFP, 128-Leads, Body 20x14 mm, Pitch 0.5mm, IPC Low Density)
part A pins: 1 CLKOUT (out), 4  RDY0/SLRD   (in), 5  RDY1/SLWR   (in), 6 RDY2 (in), 7 RDY3 (in), 8 RDY4 (in), 9 RDY5 (in), 11 XTALOUT (out), 12 XTALIN (in), 18 DPLUS (io), 19 DMINUS (io), 21 A11 (out), 22 A12 (out), 23 A13 (out), 24 A14 (out), 25 A15 (out), 28 INT4 (in), 29 T0 (in), 30 T1 (in), 31 T2 (in), 32  IFCLK (io), 34 BKPT (out), 35 EA (in), 36 SCL (out), 37 SDA (out), 38 ~{OE} (out), 39 ~{PSEN} (out), 40 ~{RD} (out), 41 ~{WR} (out), 42 ~{CS} (out), 44 PB0/FD[0]   (io), 45 PB1/FD[1]   (io), 46 PB2/FD[2]   (io), 47 PB3/FD[3]   (io), 50 TXD0 (out), 51 RXD0 (in), 52 TXD1 (out), 53 RXD1 (in), 54 PB4/FD[4]   (io), 55 PB5/FD[5]   (io), 56 PB6/FD[6]   (io), 57 PB7/FD[7]   (io), 59 D0 (io), 60 D1 (io), 61 D2 (io), 62 D3 (io), 63 D4 (io), 66 CTL3 (out), 67 CTL4 (out), 69 CTL0/FLAGA   (out), 70 CTL1/FLAGB   (out), 71 CTL2/FLAGC   (out), 72 PC0/GPIFADR0   (io), 73 PC1/GPIFADR1   (io), 74 PC2/GPIFADR2   (io), 75 PC3/GPIFADR3   (io), 76 PC4/GPIFADR4   (io), 77 PC5/GPIFADR5   (io), 78 PC6/GPIFADR6   (io), 79 PC7/GPIFADR7   (io), 82 PA0/~{INT}0   (io), 83 PA1/~{INT1} (io), 84 PA2/SLOE/  (io), 85 PA3/WU2   (io), 86 D5 (io), 87 D6 (io), 88 D7 (io), 89 PA4/FIFOADR0   (io), 90 PA5/FIFOADR1   (io), 91 PA6/PKTEND   (io), 92 PA7/FLAGD/~{SLCS} (io), 94 A0 (out), 95 A1 (out), 96 A2 (out), 97 A3 (out), 98 CTL5 (out), 99 ~{RESET} (in), 101 WAKEUP (in), 102 PD0/FD[8]   (io), 103 PD1/FD[9]   (io), 104 PD2/FD[10]   (io), 105 PD3/FD[11]   (io), 106 ~{INT5} (in), 108 PE0/T0OUT   (io), 109 PE1/T1OUT   (io), 110 PE2/T2OUT   (io), 111 PE3/RXD0OUT   (io), 112 PE4/RXD1OUT   (io), 113 PE5/INT6   (io), 114 PE6/T2EX   (io), 115 PE7/GPIFADR8   (io), 117 A4 (out), 118 A5 (out), 119 A6 (out), 120 A7 (out), 121 PD4/FD[12]   (io), 122 PD5/FD[13]   (io), 123 PD6/FD[14]   (io), 124 PD7/FD[15]   (io), 126 A8 (out), 127 A9 (out), 128 A10 (out)
part B pins: 2 VCC (power), 3 GND (power), 10 AVCC (power), 13 AGND (power), 14 NC, 15 NC, 16 NC, 17 AVCC (power), 20 AGND (power), 26 VCC (power), 27 GND (power), 33 Reserved (power), 43 VCC (power), 48 VCC (power), 49 GND (power), 58 GND (power), 64 VCC (power), 65 GND (power), 68 VCC (power), 80 GND (power), 81 VCC (power), 93 GND (power), 100 VCC (power), 107 VCC (power), 116 GND (power), 125 GND (power)

## CY7C68014A-56BAXC
designator U?
EZ-USB FX2LP USB Microcontroller Ideal for Battery Powered Applications,16K RAM, 24 I/Os, 56-Pin VFBGA, Pb-Free, Commercial Grade
footprint BZ56 (BGA, 56-Leads, Body 5x5mm, Pitch 0.5mm)
pins: A1  RDY0/SLRD   (in), A2 PD7/FD[15]   (io) "Port D", A3 PD5/FD[13]   (io) "Port D", A4 GND (power), A5 VCC (power), A6 PD3/FD[11]   (io) "Port D", A7 PD1/FD[9]   (io) "Port D", A8 PD0/FD[8]   (io) "Port D", B1  RDY1/SLWR   (in), B2 CLKOUT (out), B3 PD4/FD[12]   (io) "Port D", B4 GND (power), B5 VCC (power), B6 PD2/FD[10]   (io) "Port D", B7 WAKEUP (in), B8 ~{RESET} (in), C1 XTALIN (in), C2 XTALOUT (out), C3 PD6/FD[14]   (io) "Port D", C4 GND (power), C5 VCC (power), C6 PA7/FLAGD/~{SLCS}   (io) "Port A", C7 PA6 orPKTEND   (io) "Port A", C8 PA5/FIFOADR1   (io) "Port A", D1 AVCC (power), D2 AVCC (power), D7 GND (power), D8 GND (power), E1 DMINUS (io), E2 DPLUS (io), E7 VCC (power), E8 VCC (power), F1 AGND (power), F2 AGND (power), F3 SCL (out), F4 PB1/FD[1]   (io) "Port B", F5 PB6/FD[6]   (io) "Port B", F6 PA4/FIFOADR0   (io) "Port A", F7 PA3/WU2   (io) "Port A", F8 PA2/SLOE (io) "Port A", G1 VCC (power), G2  IFCLK  (io), G3 SDA (out), G4 PB3/FD[3]   (io) "Port B", G5 PB5/FD[5]   (io) "Port B", G6 PA1/~{INT1}   (io) "Port A", G7 CTL1/FLAGB   (out), G8 PA0/~{INT0}   (io) "Port A", H1 GND (power), H2 RESERVED (in), H3 PB0/FD[0]   (io) "Port B", H4 PB2/FD[2]   (io) "Port B", H5 PB4/FD[4]   (io) "Port B", H6 PB7/FD[7]   (io) "Port B", H7 CTL0/FLAGA   (out), H8 CTL2/FLAGC   (out)

## CY7C68014A-56LFXC
designator U?
EZ-USB FX2LP USB Microcontroller Ideal for Battery Powered Applications,16K RAM, 24 I/Os, 56-Pin QFN, Pb-Free, Commercial Grade
footprint LF56A_N (QFN, 56-Leads, Body 8x8mm, Pitch 0.5mm, IPC Medium Density)
footprint LF56A_L (QFN, 56-Leads, Body 8x8mm, Pitch 0.5mm, IPC High Density)
footprint LF56A_M (QFN, 56-Leads, Body 8x8mm, Pitch 0.5mm, IPC Low Density)
pins: 1  RDY0/SLRD   (in), 2  RDY1/SLWR   (in), 3 AVCC (power), 4 XTALOUT (out), 5 XTALIN (in), 6 AGND (power), 7 AVCC (power), 8 DPLUS (io), 9 DMINUS (io), 10 AGND (power), 11 VCC (power), 12 GND (power), 13  IFCLK (io), 14 RESERVED (in), 15 SCL (out), 16 SDA (out), 17 VCC (power), 18 PB0/FD[0]   (io) "Port B", 19 PB1/FD[1]   (io) "Port B", 20 PB2/FD[2]   (io) "Port B", 21 PB3/FD[3]   (io) "Port B", 22 PB4/FD[4]   (io) "Port B", 23 PB5/FD[5]   (io) "Port B", 24 PB6/FD[6]   (io) "Port B", 25 PB7/FD[7]   (io) "Port B", 26 GND (power), 27 VCC (power), 28 GND (power), 29 CTL0/FLAGA   (out), 30 CTL1/FLAGB   (out), 31 CTL2/FLAGC   (out), 32 VCC (power), 33 PA0/~{INT0} (io) "Port A", 34 PA1/~{INT1} (io) "Port A", 35 PA2/SLOE (io) "Port A", 36 PA3/WU2   (io) "Port A", 37 PA4/FIFOADR0   (io) "Port A", 38 PA5/FIFOADR1   (io) "Port A", 39 PA6 orPKTEND   (io) "Port A", 40 PA7/FLAGD/~{SLCS} (io) "Port A", 41 GND (power), 42 ~{RESET} (in), 43 VCC (power), 44 WAKEUP (in), 45 PD0/FD[8]   (io) "Port D", 46 PD1/FD[9]   (io) "Port D", 47 PD2/FD[10]   (io) "Port D", 48 PD3/FD[11]   (io) "Port D", 49 PD4/FD[12]   (io) "Port D", 50 PD5/FD[13]   (io) "Port D", 51 PD6/FD[14]   (io) "Port D", 52 PD7/FD[15]   (io) "Port D", 53 GND (power), 54 CLKOUT (out), 55 VCC (power), 56 GND (power), 57 Thermal Pad (power)

## CY7C68014A-56PVXC
designator U?
EZ-USB FX2LP USB Microcontroller Ideal for Battery Powered Applications,16K RAM, 24 I/Os, 56-Pin SSOP, Pb-Free, Commercial Grade
footprint O56 (SSOP; 56 Leads; Body Width 7.5 mm; Pitch 0.635 mm)
pins: 1 PD5/FD[13]   (io) "Port D", 2 PD6/FD[14]   (io) "Port D", 3 PD7/FD[15]   (io) "Port D", 4 GND (power), 5 CLKOUT (out), 6 VCC (power), 7 GND (power), 8  RDY0/SLRD   (in), 9  RDY1/SLWR   (in), 10 AVCC (power), 11 XTALOUT (out), 12 XTALIN (in), 13 AGND (power), 14 AVCC (power), 15 DPLUS (io), 16 DMINUS (io), 17 AGND (power), 18 VCC (power), 19 GND (power), 20  IFCLK (io), 21 RESERVED (in), 22 SCL (out), 23 SDA (out), 24 VCC (power), 25 PB0/FD[0]   (io) "Port B", 26 PB1/FD[1]   (io) "Port B", 27 PB2/FD[2]   (io) "Port B", 28 PB3/FD[3]   (io) "Port B", 29 PB4/FD[4]   (io) "Port B", 30 PB5/FD[5]   (io) "Port B", 31 PB6/FD[6]   (io) "Port B", 32 PB7/FD[7]   (io) "Port B", 33 GND (power), 34 VCC (power), 35 GND (power), 36 CTL0/FLAGA   (out), 37 CTL1/FLAGB   (out), 38 CTL2/FLAGC   (out), 39 VCC (power), 40 PA0/~{INT0} (io) "Port A", 41 PA1/~{INT1} (io) "Port A", 42 PA2/SLOE (io) "Port A", 43 PA3/WU2   (io) "Port A", 44 PA4/FIFOADR0   (io) "Port A", 45 PA5/FIFOADR1   (io) "Port A", 46 PA6 orPKTEND   (io) "Port A", 47 PA7/FLAGD/~{SLCS} (io) "Port A", 48 GND (power), 49 ~{RESET} (in), 50 VCC (power), 51 WAKEUP (in), 52 PD0/FD[8]   (io) "Port D", 53 PD1/FD[9]   (io) "Port D", 54 PD2/FD[10]   (io) "Port D", 55 PD3/FD[11]   (io) "Port D", 56 PD4/FD[12]   (io) "Port D"

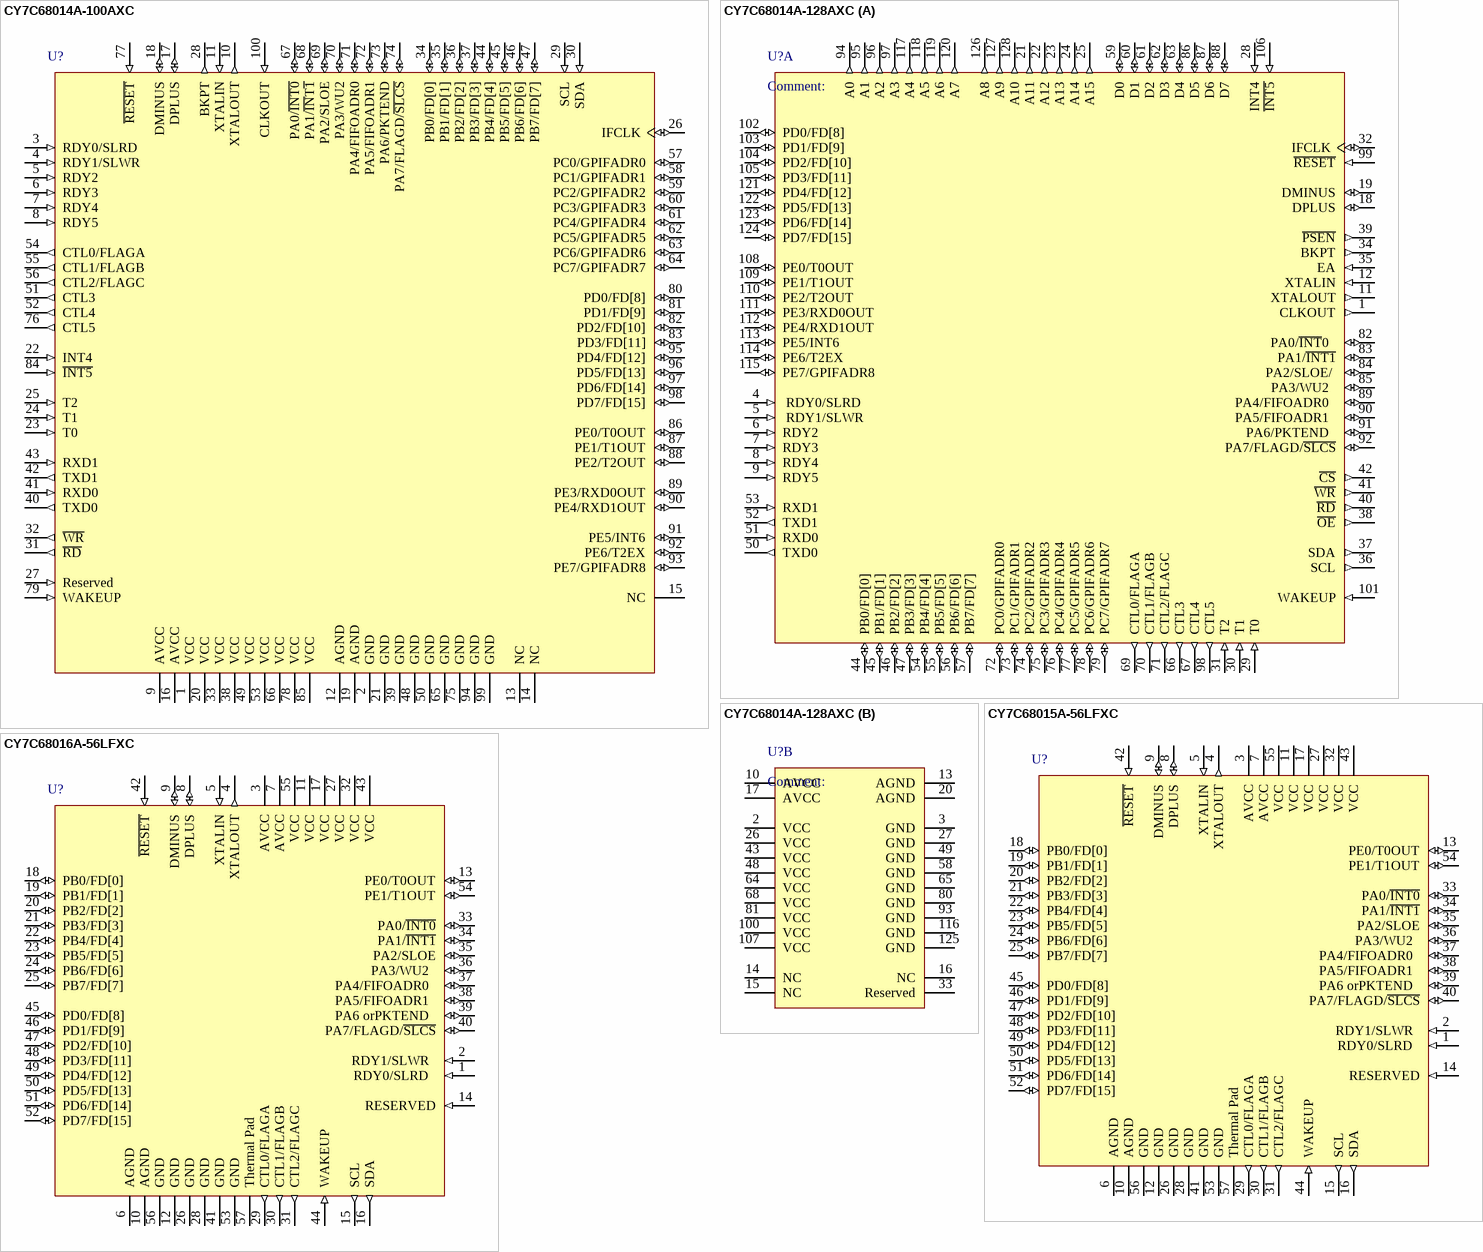
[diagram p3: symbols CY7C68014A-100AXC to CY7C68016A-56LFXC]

## CY7C68014A-100AXC
designator U?
EZ-USB FX2LP USB Microcontroller Ideal for Battery Powered Applications,16K RAM, 40 I/Os, 100-Pin TQFP, Pb-Free, Commercial Grade
footprint A101_N (Thin QFP, 100-Leads, Body 20x14mm, Pitch 0.65mm, IPC Medium Density)
footprint A101_L (Thin QFP, 100-Leads, Body 20x14mm, Pitch 0.65mm, IPC High Density)
footprint A101_M (Thin QFP, 100-Leads, Body 20x14mm, Pitch 0.65mm, IPC Low Density)
pins: 1 VCC (power), 2 GND (power), 3 RDY0/SLRD (in), 4 RDY1/SLWR (in), 5 RDY2 (in), 6 RDY3 (in), 7 RDY4 (in), 8 RDY5 (in), 9 AVCC (power), 10 XTALOUT (out), 11 XTALIN (in), 12 AGND (power), 13 NC, 14 NC, 15 NC, 16 AVCC (power), 17 DPLUS (io), 18 DMINUS (io), 19 AGND (power), 20 VCC (power), 21 GND (power), 22 INT4 (in), 23 T0 (in), 24 T1 (in), 25 T2 (in), 26 IFCLK (io), 27 Reserved (in), 28 BKPT (out), 29 SCL (in), 30 SDA (in), 31 ~{RD} (out), 32 ~{WR} (out), 33 VCC (power), 34 PB0/FD[0] (io) "Port B", 35 PB1/FD[1] (io) "Port B", 36 PB2/FD[2] (io) "Port B", 37 PB3/FD[3] (io) "Port B", 38 VCC (power), 39 GND (power), 40 TXD0 (out), 41 RXD0 (in), 42 TXD1 (out), 43 RXD1 (in), 44 PB4/FD[4] (io) "Port B", 45 PB5/FD[5] (io) "Port B", 46 PB6/FD[6] (io) "Port B", 47 PB7/FD[7] (io) "Port B", 48 GND (power), 49 VCC (power), 50 GND (power), 51 CTL3 (out), 52 CTL4 (out), 53 VCC (power), 54 CTL0/FLAGA (out), 55 CTL1/FLAGB (out), 56 CTL2/FLAGC (out), 57 PC0/GPIFADR0 (io) "Port C", 58 PC1/GPIFADR1 (io) "Port C", 59 PC2/GPIFADR2 (io) "Port C", 60 PC3/GPIFADR3 (io) "Port C", 61 PC4/GPIFADR4 (io) "Port C", 62 PC5/GPIFADR5 (io) "Port C", 63 PC6/GPIFADR6 (io) "Port C", 64 PC7/GPIFADR7 (io) "Port C", 65 GND (power), 66 VCC (power), 67 PA0/~{INT0} (io) "Port A", 68 PA1/~{IN}T~{1} (io) "Port A", 69 PA2/SLOE (io) "Port A", 70 PA3/WU2 (io) "Port A", 71 PA4/FIFOADR0 (io) "Port A", 72 PA5/FIFOADR1 (io) "Port A", 73 PA6/PKTEND (io) "Port A", 74 PA7/FLAGD/~{SLCS} (io) "Port A", 75 GND (power), 76 CTL5 (out), 77 ~{RESET} (in), 78 VCC (power), 79 WAKEUP (in), 80 PD0/FD[8] (io) "Port D", 81 PD1/FD[9] (io) "Port D", 82 PD2/FD[10] (io) "Port D", 83 PD3/FD[11] (io) "Port D", 84 ~{INT5} (in), 85 VCC (power), 86 PE0/T0OUT (io) "Port E", 87 PE1/T1OUT (io) "Port E", 88 PE2/T2OUT (io) "Port E", 89 PE3/RXD0OUT (io) "Port E", 90 PE4/RXD1OUT (io) "Port E", 91 PE5/INT6 (io) "Port E", 92 PE6/T2EX (io) "Port E", 93 PE7/GPIFADR8 (io) "Port E", 94 GND (power), 95 PD4/FD[12] (io) "Port D", 96 PD5/FD[13] (io) "Port D", 97 PD6/FD[14] (io) "Port D", 98 PD7/FD[15] (io) "Port D", 99 GND (power), 100 CLKOUT (in)

## CY7C68014A-128AXC
designator U?
EZ-USB FX2LP USB Microcontroller Ideal for Battery Powered Applications,16K RAM, 40 I/Os, 128-Pin TQFP, Pb-Free, Commercial Grade
footprint A128_N (Thin QFP, 128-Leads, Body 20x14 mm, Pitch 0.5mm, IPC Medium Density)
footprint A128_L (Thin QFP, 128-Leads, Body 20x14 mm, Pitch 0.5mm, IPC High Density)
footprint A128_M (Thin QFP, 128-Leads, Body 20x14 mm, Pitch 0.5mm, IPC Low Density)
part A pins: 1 CLKOUT (out), 4  RDY0/SLRD   (in), 5  RDY1/SLWR   (in), 6 RDY2 (in), 7 RDY3 (in), 8 RDY4 (in), 9 RDY5 (in), 11 XTALOUT (out), 12 XTALIN (in), 18 DPLUS (io), 19 DMINUS (io), 21 A11 (out), 22 A12 (out), 23 A13 (out), 24 A14 (out), 25 A15 (out), 28 INT4 (in), 29 T0 (in), 30 T1 (in), 31 T2 (in), 32  IFCLK (io), 34 BKPT (out), 35 EA (in), 36 SCL (out), 37 SDA (out), 38 ~{OE} (out), 39 ~{PSEN} (out), 40 ~{RD} (out), 41 ~{WR} (out), 42 ~{CS} (out), 44 PB0/FD[0]   (io), 45 PB1/FD[1]   (io), 46 PB2/FD[2]   (io), 47 PB3/FD[3]   (io), 50 TXD0 (out), 51 RXD0 (in), 52 TXD1 (out), 53 RXD1 (in), 54 PB4/FD[4]   (io), 55 PB5/FD[5]   (io), 56 PB6/FD[6]   (io), 57 PB7/FD[7]   (io), 59 D0 (io), 60 D1 (io), 61 D2 (io), 62 D3 (io), 63 D4 (io), 66 CTL3 (out), 67 CTL4 (out), 69 CTL0/FLAGA   (out), 70 CTL1/FLAGB   (out), 71 CTL2/FLAGC   (out), 72 PC0/GPIFADR0   (io), 73 PC1/GPIFADR1   (io), 74 PC2/GPIFADR2   (io), 75 PC3/GPIFADR3   (io), 76 PC4/GPIFADR4   (io), 77 PC5/GPIFADR5   (io), 78 PC6/GPIFADR6   (io), 79 PC7/GPIFADR7   (io), 82 PA0/~{INT}0   (io), 83 PA1/~{INT1} (io), 84 PA2/SLOE/  (io), 85 PA3/WU2   (io), 86 D5 (io), 87 D6 (io), 88 D7 (io), 89 PA4/FIFOADR0   (io), 90 PA5/FIFOADR1   (io), 91 PA6/PKTEND   (io), 92 PA7/FLAGD/~{SLCS} (io), 94 A0 (out), 95 A1 (out), 96 A2 (out), 97 A3 (out), 98 CTL5 (out), 99 ~{RESET} (in), 101 WAKEUP (in), 102 PD0/FD[8]   (io), 103 PD1/FD[9]   (io), 104 PD2/FD[10]   (io), 105 PD3/FD[11]   (io), 106 ~{INT5} (in), 108 PE0/T0OUT   (io), 109 PE1/T1OUT   (io), 110 PE2/T2OUT   (io), 111 PE3/RXD0OUT   (io), 112 PE4/RXD1OUT   (io), 113 PE5/INT6   (io), 114 PE6/T2EX   (io), 115 PE7/GPIFADR8   (io), 117 A4 (out), 118 A5 (out), 119 A6 (out), 120 A7 (out), 121 PD4/FD[12]   (io), 122 PD5/FD[13]   (io), 123 PD6/FD[14]   (io), 124 PD7/FD[15]   (io), 126 A8 (out), 127 A9 (out), 128 A10 (out)
part B pins: 2 VCC (power), 3 GND (power), 10 AVCC (power), 13 AGND (power), 14 NC, 15 NC, 16 NC, 17 AVCC (power), 20 AGND (power), 26 VCC (power), 27 GND (power), 33 Reserved (power), 43 VCC (power), 48 VCC (power), 49 GND (power), 58 GND (power), 64 VCC (power), 65 GND (power), 68 VCC (power), 80 GND (power), 81 VCC (power), 93 GND (power), 100 VCC (power), 107 VCC (power), 116 GND (power), 125 GND (power)

## CY7C68015A-56LFXC
designator U?
EZ-USB FX2LP USB Microcontroller Ideal for Non-Battery Powered Applications,16K RAM, 26 I/Os, 56-Pin QFN, Pb-Free, Commercial Grade
footprint LF56A_N (QFN, 56-Leads, Body 8x8mm, Pitch 0.5mm, IPC Medium Density)
footprint LF56A_L (QFN, 56-Leads, Body 8x8mm, Pitch 0.5mm, IPC High Density)
footprint LF56A_M (QFN, 56-Leads, Body 8x8mm, Pitch 0.5mm, IPC Low Density)
pins: 1  RDY0/SLRD   (in), 2  RDY1/SLWR   (in), 3 AVCC (power), 4 XTALOUT (out), 5 XTALIN (in), 6 AGND (power), 7 AVCC (power), 8 DPLUS (io), 9 DMINUS (io), 10 AGND (power), 11 VCC (power), 12 GND (power), 13 PE0/T0OUT (io), 14 RESERVED (in), 15 SCL (out), 16 SDA (out), 17 VCC (power), 18 PB0/FD[0]   (io) "Port B", 19 PB1/FD[1]   (io) "Port B", 20 PB2/FD[2]   (io) "Port B", 21 PB3/FD[3]   (io) "Port B", 22 PB4/FD[4]   (io) "Port B", 23 PB5/FD[5]   (io) "Port B", 24 PB6/FD[6]   (io) "Port B", 25 PB7/FD[7]   (io) "Port B", 26 GND (power), 27 VCC (power), 28 GND (power), 29 CTL0/FLAGA   (out), 30 CTL1/FLAGB   (out), 31 CTL2/FLAGC   (out), 32 VCC (power), 33 PA0/~{INT0} (io) "Port A", 34 PA1/~{INT1} (io) "Port A", 35 PA2/SLOE (io) "Port A", 36 PA3/WU2   (io) "Port A", 37 PA4/FIFOADR0   (io) "Port A", 38 PA5/FIFOADR1   (io) "Port A", 39 PA6 orPKTEND   (io) "Port A", 40 PA7/FLAGD/~{SLCS} (io) "Port A", 41 GND (power), 42 ~{RESET} (in), 43 VCC (power), 44 WAKEUP (in), 45 PD0/FD[8]   (io) "Port D", 46 PD1/FD[9]   (io) "Port D", 47 PD2/FD[10]   (io) "Port D", 48 PD3/FD[11]   (io) "Port D", 49 PD4/FD[12]   (io) "Port D", 50 PD5/FD[13]   (io) "Port D", 51 PD6/FD[14]   (io) "Port D", 52 PD7/FD[15]   (io) "Port D", 53 GND (power), 54 PE1/T1OUT (io), 55 VCC (power), 56 GND (power), 57 Thermal Pad (power)

## CY7C68016A-56LFXC
designator U?
EZ-USB FX2LP USB Microcontroller Ideal for Battery Powered Applications,16K RAM, 26 I/Os, 56-Pin QFN, Pb-Free, Commercial Grade
footprint LF56A_N (QFN, 56-Leads, Body 8x8mm, Pitch 0.5mm, IPC Medium Density)
footprint LF56A_L (QFN, 56-Leads, Body 8x8mm, Pitch 0.5mm, IPC High Density)
footprint LF56A_M (QFN, 56-Leads, Body 8x8mm, Pitch 0.5mm, IPC Low Density)
pins: 1  RDY0/SLRD   (in), 2  RDY1/SLWR   (in), 3 AVCC (power), 4 XTALOUT (out), 5 XTALIN (in), 6 AGND (power), 7 AVCC (power), 8 DPLUS (io), 9 DMINUS (io), 10 AGND (power), 11 VCC (power), 12 GND (power), 13 PE0/T0OUT (io), 14 RESERVED (in), 15 SCL (out), 16 SDA (out), 17 VCC (power), 18 PB0/FD[0]   (io) "Port B", 19 PB1/FD[1]   (io) "Port B", 20 PB2/FD[2]   (io) "Port B", 21 PB3/FD[3]   (io) "Port B", 22 PB4/FD[4]   (io) "Port B", 23 PB5/FD[5]   (io) "Port B", 24 PB6/FD[6]   (io) "Port B", 25 PB7/FD[7]   (io) "Port B", 26 GND (power), 27 VCC (power), 28 GND (power), 29 CTL0/FLAGA   (out), 30 CTL1/FLAGB   (out), 31 CTL2/FLAGC   (out), 32 VCC (power), 33 PA0/~{INT0} (io) "Port A", 34 PA1/~{INT1} (io) "Port A", 35 PA2/SLOE (io) "Port A", 36 PA3/WU2   (io) "Port A", 37 PA4/FIFOADR0   (io) "Port A", 38 PA5/FIFOADR1   (io) "Port A", 39 PA6 orPKTEND   (io) "Port A", 40 PA7/FLAGD/~{SLCS} (io) "Port A", 41 GND (power), 42 ~{RESET} (in), 43 VCC (power), 44 WAKEUP (in), 45 PD0/FD[8]   (io) "Port D", 46 PD1/FD[9]   (io) "Port D", 47 PD2/FD[10]   (io) "Port D", 48 PD3/FD[11]   (io) "Port D", 49 PD4/FD[12]   (io) "Port D", 50 PD5/FD[13]   (io) "Port D", 51 PD6/FD[14]   (io) "Port D", 52 PD7/FD[15]   (io) "Port D", 53 GND (power), 54 PE1/T1OUT (io), 55 VCC (power), 56 GND (power), 57 Thermal Pad (power)

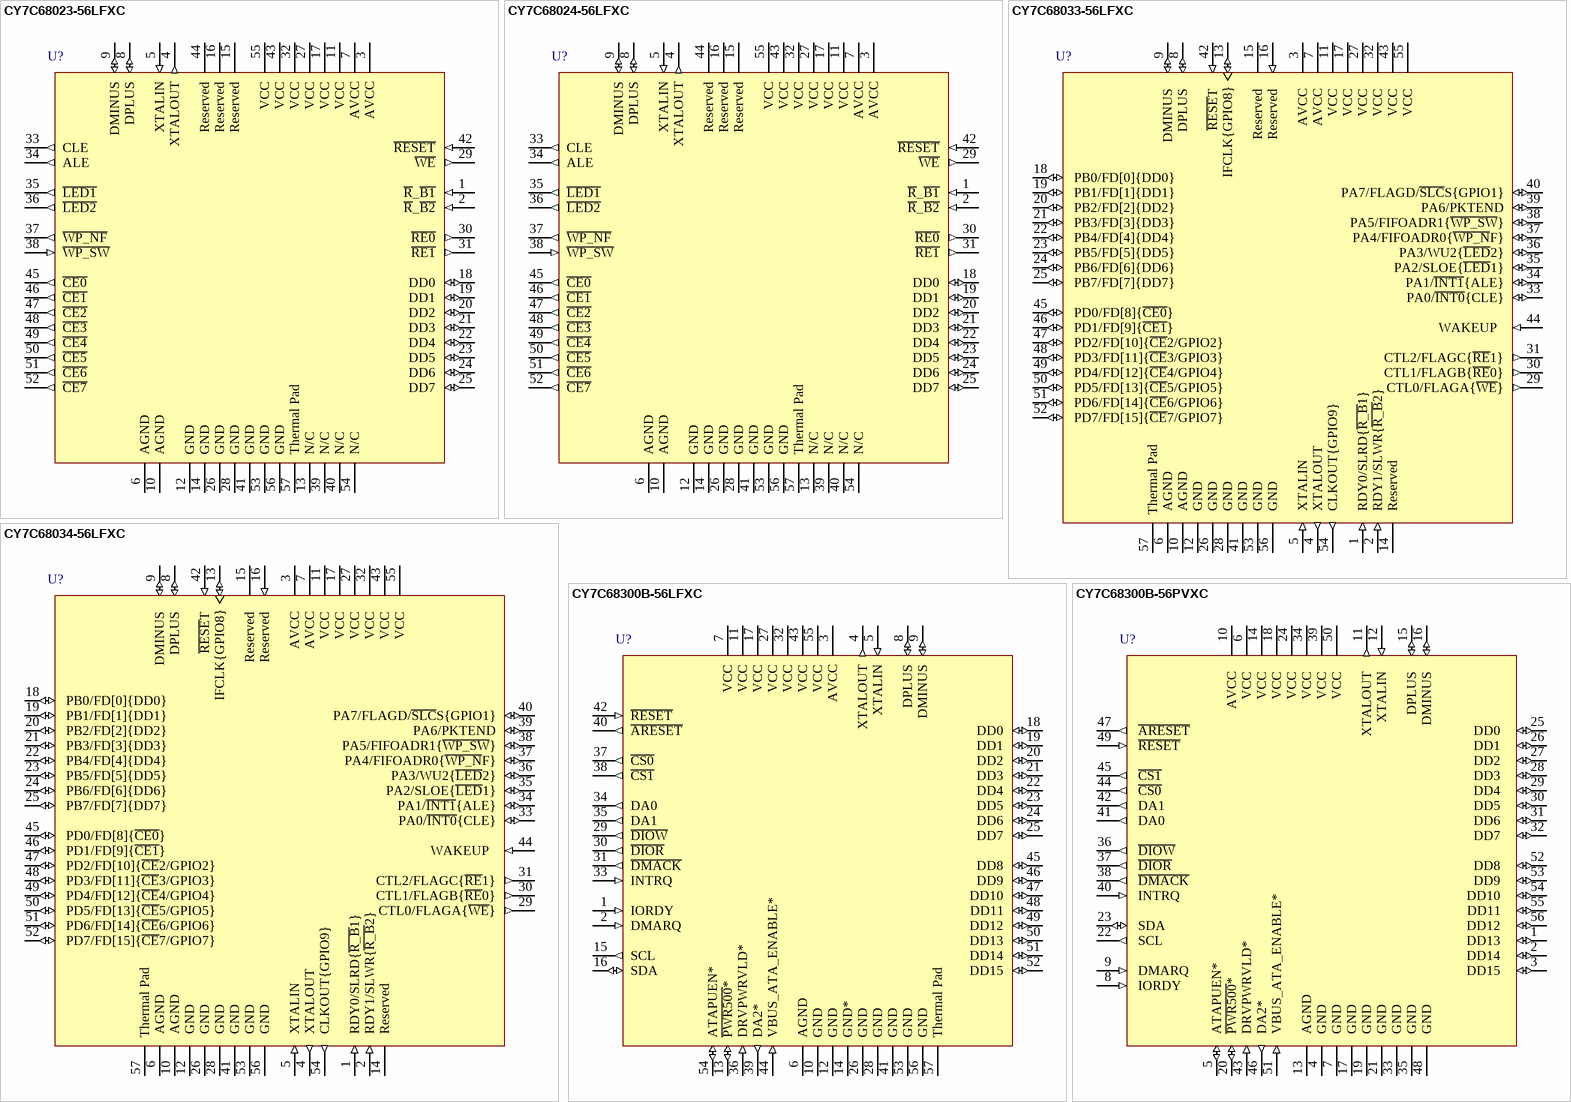
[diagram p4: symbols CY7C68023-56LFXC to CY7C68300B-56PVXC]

## CY7C68023-56LFXC
designator U?
EZ-USB NX2LP USB 2.0 NAND Flash Controller for Self/ Bus Power, 56 - pin QFN, Pb-Free
footprint LF56A_N (QFN, 56-Leads, Body 8x8mm, Pitch 0.5mm, IPC Medium Density)
footprint LF56A_L (QFN, 56-Leads, Body 8x8mm, Pitch 0.5mm, IPC High Density)
footprint LF56A_M (QFN, 56-Leads, Body 8x8mm, Pitch 0.5mm, IPC Low Density)
pins: 1 ~{R}_~{B1} (in), 2 ~{R}_~{B2} (in), 3 AVCC (power), 4 XTALOUT (out), 5 XTALIN (in), 6 AGND (power), 7 AVCC (power), 8 DPLUS (io), 9 DMINUS (io), 10 AGND (power), 11 VCC (power), 12 GND (power), 13 N/C, 14 GND (power), 15 Reserved (power), 16 Reserved (power), 17 VCC (power), 18 DD0 (io), 19 DD1 (io), 20 DD2 (io), 21 DD3 (io), 22 DD4 (io), 23 DD5 (io), 24 DD6 (io), 25 DD7 (io), 26 GND (power), 27 VCC (power), 28 GND (power), 29 ~{WE} (out), 30 ~{RE0} (out), 31 ~{RE1} (out), 32 VCC (power), 33 CLE (out), 34 ALE (out), 35 ~{LED1} (out), 36 ~{LED2} (out), 37 ~{WP_NF} (out), 38 ~{WP_SW} (in), 39 N/C, 40 N/C, 41 GND (power), 42 ~{RESET} (in), 43 VCC (power), 44 Reserved (power), 45 ~{CE0} (out), 46 ~{CE1} (out), 47 ~{CE2} (out), 48 ~{CE3} (out), 49 ~{CE4} (out), 50 ~{CE5} (out), 51 ~{CE6} (out), 52 ~{CE7} (out), 53 GND (power), 54 N/C, 55 VCC (power), 56 GND (power), 57 Thermal Pad (power)

## CY7C68024-56LFXC
designator U?
EZ-USB NX2LP USB 2.0 NAND Flash Controller for Battery Power, 56 - pin QFN, Pb-Free
footprint LF56A_N (QFN, 56-Leads, Body 8x8mm, Pitch 0.5mm, IPC Medium Density)
footprint LF56A_L (QFN, 56-Leads, Body 8x8mm, Pitch 0.5mm, IPC High Density)
footprint LF56A_M (QFN, 56-Leads, Body 8x8mm, Pitch 0.5mm, IPC Low Density)
pins: 1 ~{R}_~{B1} (in), 2 ~{R}_~{B2} (in), 3 AVCC (power), 4 XTALOUT (out), 5 XTALIN (in), 6 AGND (power), 7 AVCC (power), 8 DPLUS (io), 9 DMINUS (io), 10 AGND (power), 11 VCC (power), 12 GND (power), 13 N/C, 14 GND (power), 15 Reserved (power), 16 Reserved (power), 17 VCC (power), 18 DD0 (io), 19 DD1 (io), 20 DD2 (io), 21 DD3 (io), 22 DD4 (io), 23 DD5 (io), 24 DD6 (io), 25 DD7 (io), 26 GND (power), 27 VCC (power), 28 GND (power), 29 ~{WE} (out), 30 ~{RE0} (out), 31 ~{RE1} (out), 32 VCC (power), 33 CLE (out), 34 ALE (out), 35 ~{LED1} (out), 36 ~{LED2} (out), 37 ~{WP_NF} (out), 38 ~{WP_SW} (in), 39 N/C, 40 N/C, 41 GND (power), 42 ~{RESET} (in), 43 VCC (power), 44 Reserved (power), 45 ~{CE0} (out), 46 ~{CE1} (out), 47 ~{CE2} (out), 48 ~{CE3} (out), 49 ~{CE4} (out), 50 ~{CE5} (out), 51 ~{CE6} (out), 52 ~{CE7} (out), 53 GND (power), 54 N/C, 55 VCC (power), 56 GND (power), 57 Thermal Pad (power)

## CY7C68033-56LFXC
designator U?
EZ-USB NX2LP-Flex USB NAND Flash Controller with enhanced 8051 Core for Non-Battery Powered Applications, 15KB RAM, 56-Pin QFN, Pb-Free; Note: Pins Names within Curly Brackets are for NAND Firmware Usage
footprint LF56A_N (QFN, 56-Leads, Body 8x8mm, Pitch 0.5mm, IPC Medium Density)
footprint LF56A_L (QFN, 56-Leads, Body 8x8mm, Pitch 0.5mm, IPC High Density)
footprint LF56A_M (QFN, 56-Leads, Body 8x8mm, Pitch 0.5mm, IPC Low Density)
pins: 1  RDY0/SLRD{~{R_B}1} (in), 2  RDY1/SLWR{~{R_B}2} (in), 3  AVCC   (power), 4  XTALOUT   (out), 5  XTALIN   (in), 6  AGND   (power), 7  AVCC   (power), 8  DPLUS   (io), 9  DMINUS   (io), 10  AGND   (power), 11  VCC   (power), 12  GND   (power), 13  IFCLK{GPIO8} (io), 14  Reserved (power), 15  Reserved   (power), 16  Reserved   (in), 17  VCC   (power), 18  PB0/FD[0]{DD0} (io) "Port B", 19  PB1/FD[1]{DD1} (io) "Port B", 20  PB2/FD[2]{DD2} (io) "Port B", 21  PB3/FD[3]{DD3} (io) "Port B", 22  PB4/FD[4]{DD4} (io) "Port B", 23  PB5/FD[5]{DD5} (io) "Port B", 24  PB6/FD[6]{DD6} (io) "Port B", 25  PB7/FD[7]{DD7} (io) "Port B", 26  GND   (power), 27  VCC   (power), 28  GND   (power), 29  CTL0/FLAGA{~{WE}} (out), 30  CTL1/FLAGB{~{RE}0} (out), 31  CTL2/FLAGC{~{RE}1} (out), 32  VCC   (power), 33  PA0/~{INT0}{CLE} (io) "Port A", 34  PA1/~{INT1}{ALE} (io) "Port A", 35  PA2/SLOE{~{LED}1} (io) "Port A", 36  PA3/WU2{~{LED}2} (io) "Port A", 37  PA4/FIFOADR0{~{WP_N}F} (io) "Port A", 38  PA5/FIFOADR1{~{WP_SW}} (io) "Port A", 39  PA6/PKTEND (io) "Port A", 40  PA7/FLAGD/~{SLC}S{GPIO1} (io) "Port A", 41  GND   (power), 42  ~{RESE}T   (in), 43  VCC   (power), 44  WAKEUP   (in) "Port A", 45  PD0/FD[8]{~{CE0}} (io) "Port D", 46  PD1/FD[9]{~{CE1}} (io) "Port D", 47  PD2/FD[10]{~{CE}2/GPIO2} (io) "Port D", 48  PD3/FD[11]{~{CE}3/GPIO3} (io) "Port D", 49  PD4/FD[12]{~{CE}4/GPIO4} (io) "Port D", 50  PD5/FD[13]{~{CE}5/GPIO5} (io) "Port D", 51  PD6/FD[14]{~{CE}6/GPIO6} (io) "Port D", 52  PD7/FD[15]{~{CE}7/GPIO7} (io) "Port D", 53  GND   (power), 54  CLKOUT{GPIO9} (out), 55  VCC   (power), 56  GND   (power), 57 Thermal Pad (power)

## CY7C68034-56LFXC
designator U?
EZ-USB NX2LP-Flex USB NAND Flash Controller with enhanced 8051 Core for Battery Powered Applications, 15KB RAM, 56-Pin QFN, Pb-Free; Note: Pins Names within Curly Brackets are for NAND Firmware Usage
footprint LF56A_N (QFN, 56-Leads, Body 8x8mm, Pitch 0.5mm, IPC Medium Density)
footprint LF56A_L (QFN, 56-Leads, Body 8x8mm, Pitch 0.5mm, IPC High Density)
footprint LF56A_M (QFN, 56-Leads, Body 8x8mm, Pitch 0.5mm, IPC Low Density)
pins: 1  RDY0/SLRD{~{R_B}1} (in), 2  RDY1/SLWR{~{R_B}2} (in), 3  AVCC   (power), 4  XTALOUT   (out), 5  XTALIN   (in), 6  AGND   (power), 7  AVCC   (power), 8  DPLUS   (io), 9  DMINUS   (io), 10  AGND   (power), 11  VCC   (power), 12  GND   (power), 13  IFCLK{GPIO8} (io), 14  Reserved (power), 15  Reserved   (power), 16  Reserved   (in), 17  VCC   (power), 18  PB0/FD[0]{DD0} (io) "Port B", 19  PB1/FD[1]{DD1} (io) "Port B", 20  PB2/FD[2]{DD2} (io) "Port B", 21  PB3/FD[3]{DD3} (io) "Port B", 22  PB4/FD[4]{DD4} (io) "Port B", 23  PB5/FD[5]{DD5} (io) "Port B", 24  PB6/FD[6]{DD6} (io) "Port B", 25  PB7/FD[7]{DD7} (io) "Port B", 26  GND   (power), 27  VCC   (power), 28  GND   (power), 29  CTL0/FLAGA{~{WE}} (out), 30  CTL1/FLAGB{~{RE}0} (out), 31  CTL2/FLAGC{~{RE}1} (out), 32  VCC   (power), 33  PA0/~{INT0}{CLE} (io) "Port A", 34  PA1/~{INT1}{ALE} (io) "Port A", 35  PA2/SLOE{~{LED}1} (io) "Port A", 36  PA3/WU2{~{LED}2} (io) "Port A", 37  PA4/FIFOADR0{~{WP_N}F} (io) "Port A", 38  PA5/FIFOADR1{~{WP_SW}} (io) "Port A", 39  PA6/PKTEND (io) "Port A", 40  PA7/FLAGD/~{SLC}S{GPIO1} (io) "Port A", 41  GND   (power), 42  ~{RESE}T   (in), 43  VCC   (power), 44  WAKEUP   (in) "Port A", 45  PD0/FD[8]{~{CE0}} (io) "Port D", 46  PD1/FD[9]{~{CE1}} (io) "Port D", 47  PD2/FD[10]{~{CE}2/GPIO2} (io) "Port D", 48  PD3/FD[11]{~{CE}3/GPIO3} (io) "Port D", 49  PD4/FD[12]{~{CE}4/GPIO4} (io) "Port D", 50  PD5/FD[13]{~{CE}5/GPIO5} (io) "Port D", 51  PD6/FD[14]{~{CE}6/GPIO6} (io) "Port D", 52  PD7/FD[15]{~{CE}7/GPIO7} (io) "Port D", 53  GND   (power), 54  CLKOUT{GPIO9} (out), 55  VCC   (power), 56  GND   (power), 57 Thermal Pad (power)

## CY7C68300B-56LFXC
designator U?
EZ-USB AT2LP USB2.0 to ATA/ATAPI Bridge for Self/Bus Powered Designs, 56-Pin QFN, Pb-Free; Note: Pin names with Asterisk denote Pin Functionality during CY7C68300A Compatibility mode
footprint LF56A_N (QFN, 56-Leads, Body 8x8mm, Pitch 0.5mm, IPC Medium Density)
footprint LF56A_L (QFN, 56-Leads, Body 8x8mm, Pitch 0.5mm, IPC High Density)
footprint LF56A_M (QFN, 56-Leads, Body 8x8mm, Pitch 0.5mm, IPC Low Density)
pins: 1 IORDY (in), 2 DMARQ (in), 3 AVCC (power), 4 XTALOUT (out), 5 XTALIN (in), 6 AGND (power), 7 VCC (power), 8 DPLUS (io), 9 DMINUS (io), 10 GND (power), 11 VCC (power), 12 GND (power), 13 ~{PWR500}* (io) "(PU 10K)", 14 GND* (power) "(RESERVED)", 15 SCL (out), 16 SDA (io), 17 VCC (power), 18 DD0 (io), 19 DD1 (io), 20 DD2 (io), 21 DD3 (io), 22 DD4 (io), 23 DD5 (io), 24 DD6 (io), 25 DD7 (io), 26 GND (power), 27 VCC (power), 28 GND (power), 29 ~{DIOW} (out), 30 ~{DIOR} (out), 31 ~{DMACK} (out), 32 VCC (power), 33 INTRQ (in), 34 DA0 (out), 35 DA1 (out), 36 DRVPWRVLD* (in) "(DA2)", 37 ~{CS0} (out), 38 ~{CS1} (out), 39 DA2* (out) "(VBUS_PWR_VALID)", 40 ~{ARESET} (out), 41 GND (power), 42 ~{RESET} (in), 43 VCC (power), 44 VBUS_ATA_ENABLE* (in) "(ATA_EN)", 45 DD8 (io), 46 DD9 (io), 47 DD10 (io), 48 DD11 (io), 49 DD12 (io), 50 DD13 (io), 51 DD14 (io), 52 DD15 (io), 53 GND (power), 54 ATAPUEN* (io) "(NC)", 55 VCC (power), 56 GND (power), 57 Thermal Pad (power)

## CY7C68300B-56PVXC
designator U?
EZ-USB AT2LP USB2.0 to ATA/ATAPI Bridge for Self/ Bus Powered Designs,56-Pin SSOP, Pb-Free; Note: Pin names with Asterisk denote Pin Functionality during CY7C68300A Compatibility mode
footprint O56 (SSOP; 56 Leads; Body Width 7.5 mm; Pitch 0.635 mm)
pins: 1  DD13   (io), 2  DD14   (io), 3  DD15   (io), 4  GND   (power), 5  ATAPUEN* (io) "(NC)", 6  VCC   (power), 7  GND   (power), 8  IORDY   (in), 9  DMARQ   (in), 10  AVCC   (power), 11  XTALOUT   (out), 12  XTALIN   (in), 13  AGND   (power), 14  VCC   (power), 15  DPLUS   (io), 16  DMINUS   (io), 17  GND   (power), 18  VCC   (power), 19  GND   (power), 20  ~{PWR500}* (io) "(PU 10K)", 21  GND (power) "(RESERVED)", 22  SCL   (out), 23  SDA   (io), 24  VCC   (power), 25  DD0   (io), 26  DD1   (io), 27  DD2   (io), 28  DD3   (io), 29  DD4   (io), 30  DD5   (io), 31  DD6   (io), 32  DD7   (io), 33  GND   (power), 34  VCC   (power), 35  GND   (power), 36  ~{DIOW} (out), 37  ~{DIOR} (out), 38  ~{DMACK} (out), 39  VCC   (power), 40  INTRQ   (in), 41  DA0   (out), 42  DA1   (out), 43  DRVPWRVLD* (in) "(DA2)", 44  ~{CS0} (out), 45  ~{CS1} (out), 46  DA2* (out) "(VBUS_PWR_VALID)", 47  ~{ARESET} (out), 48  GND   (power), 49  ~{RESET}   (in), 50  VCC   (power), 51  VBUS_ATA_ENABLE* (in) "(ATA_EN)", 52  DD8   (io), 53  DD9   (io), 54  DD10   (io), 55  DD11   (io), 56  DD12   (io)

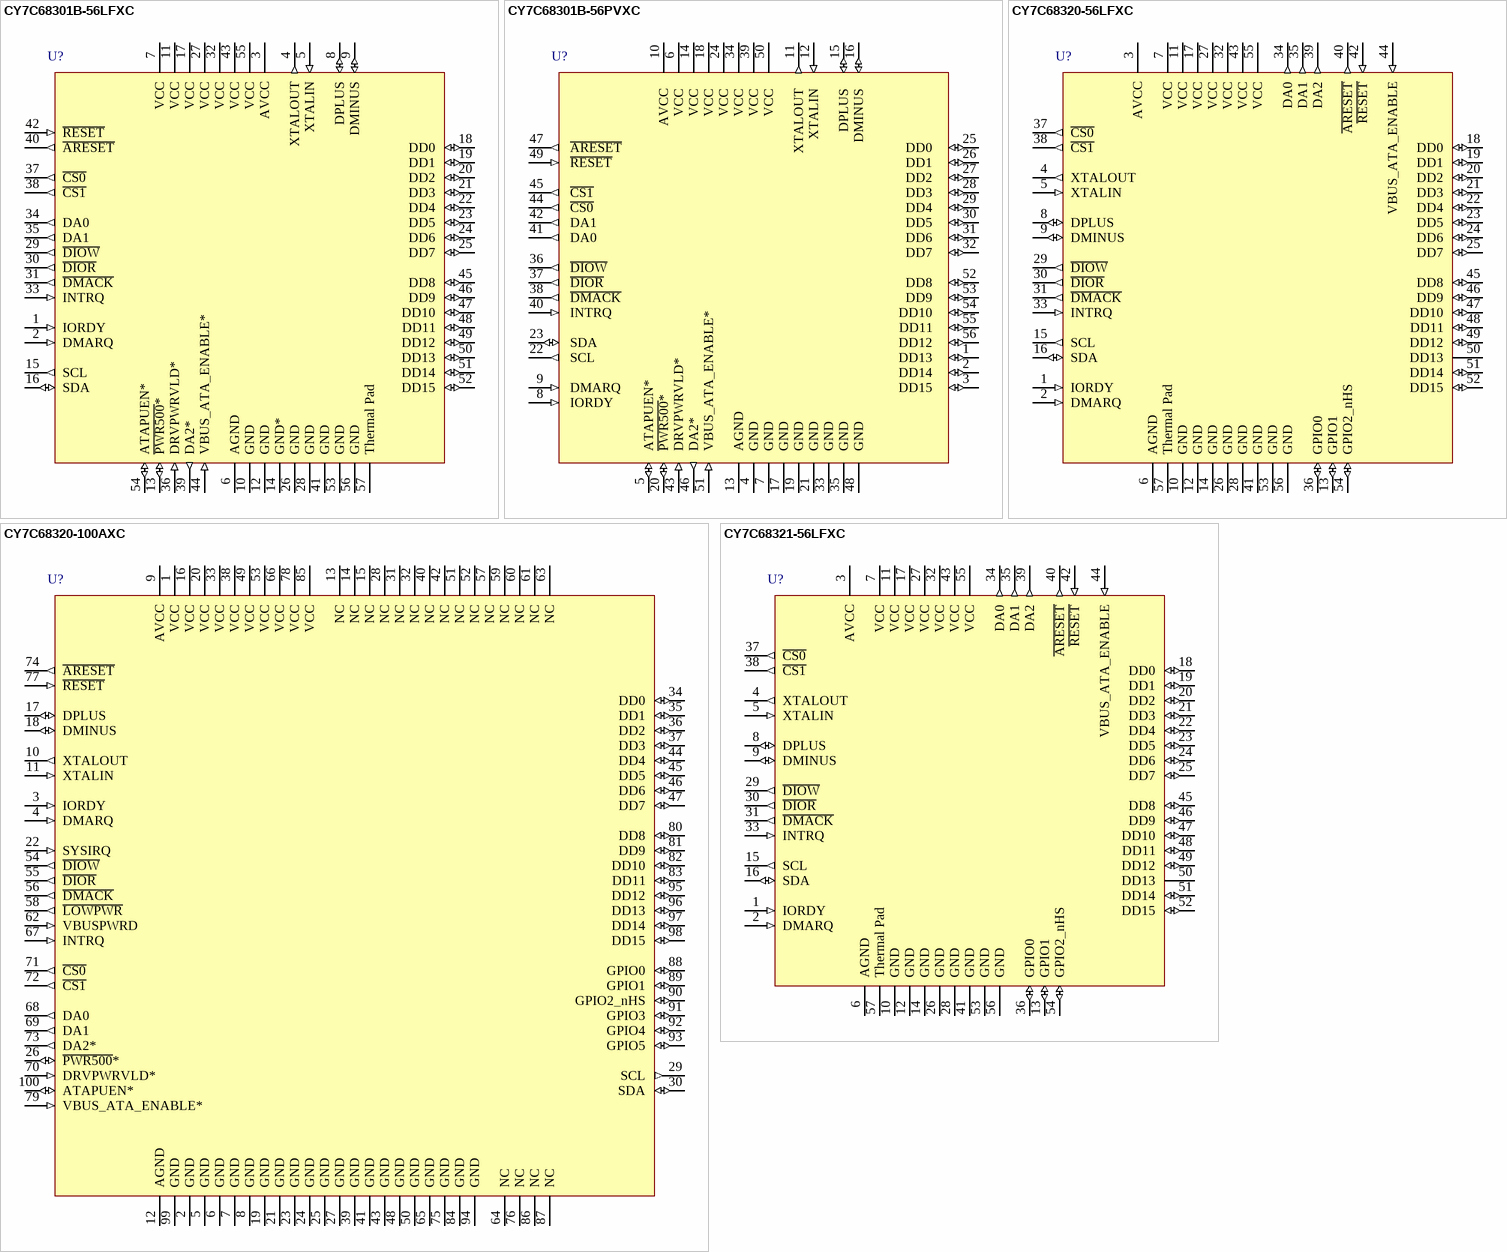
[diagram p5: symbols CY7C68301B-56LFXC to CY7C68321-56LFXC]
